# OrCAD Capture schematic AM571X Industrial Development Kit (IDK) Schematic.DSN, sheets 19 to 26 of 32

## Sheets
19 Pg06: Power Supply 2: size C
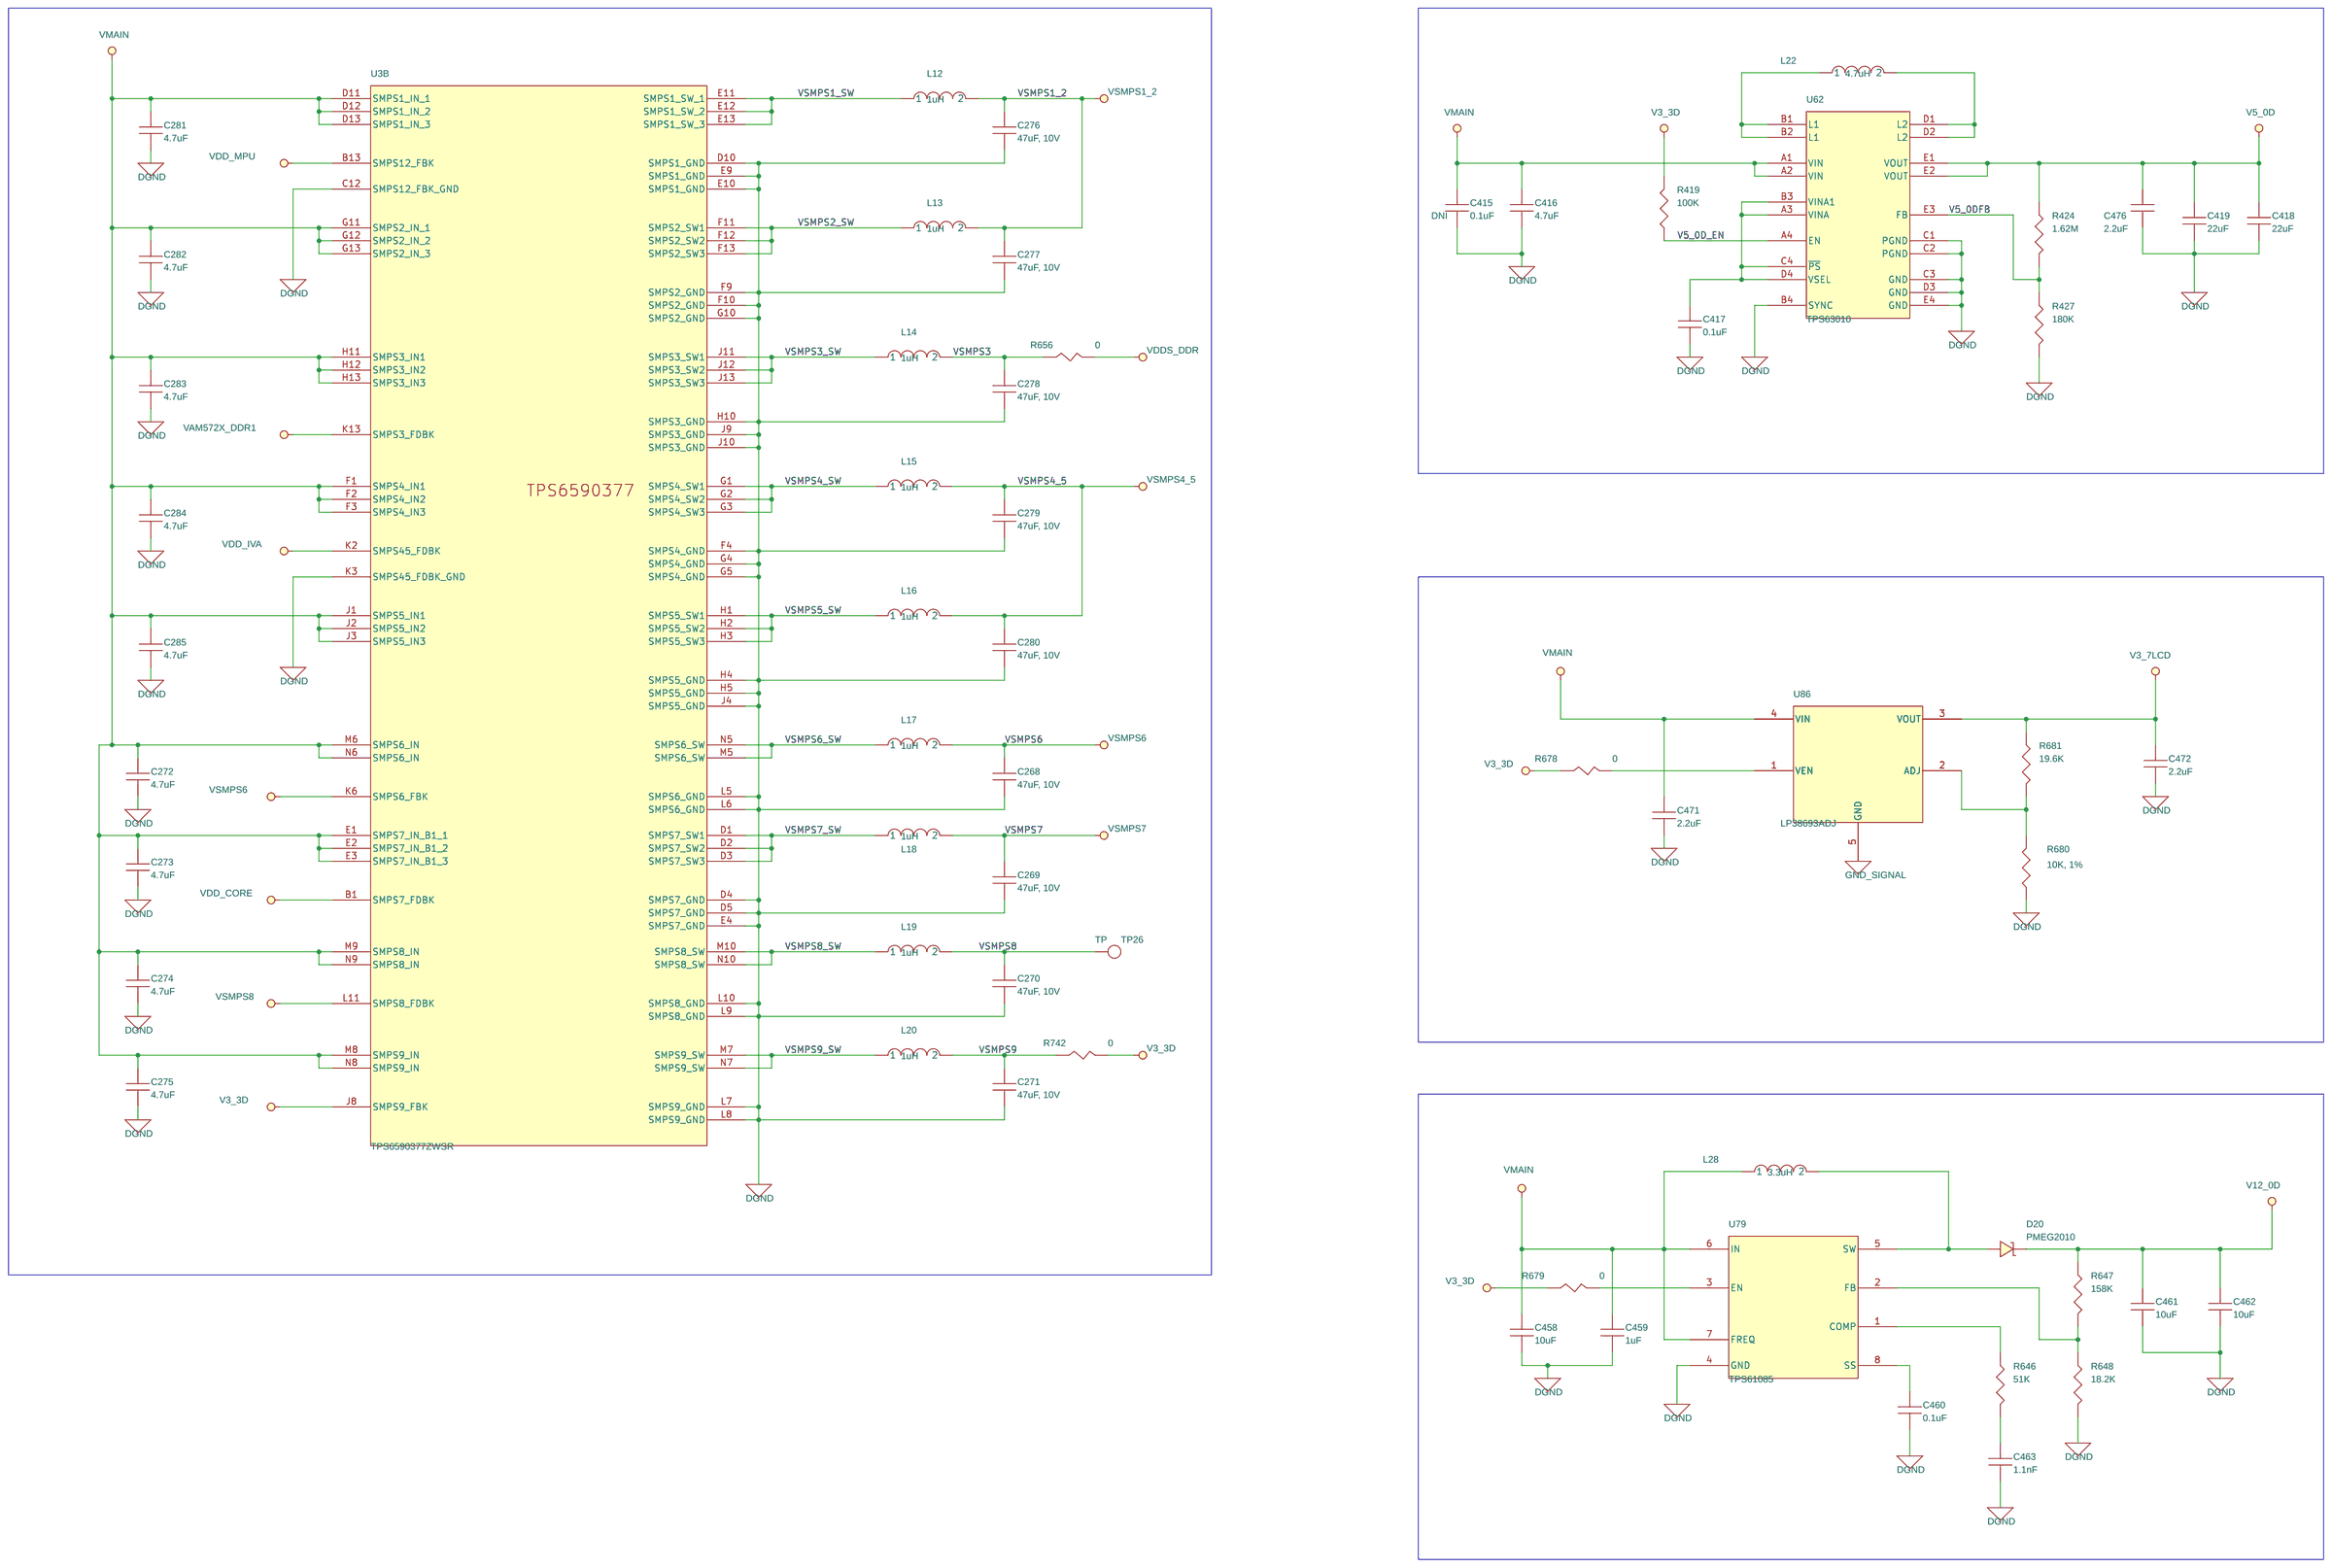
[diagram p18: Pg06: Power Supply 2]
20 Pg30: PCIE Connector: size C
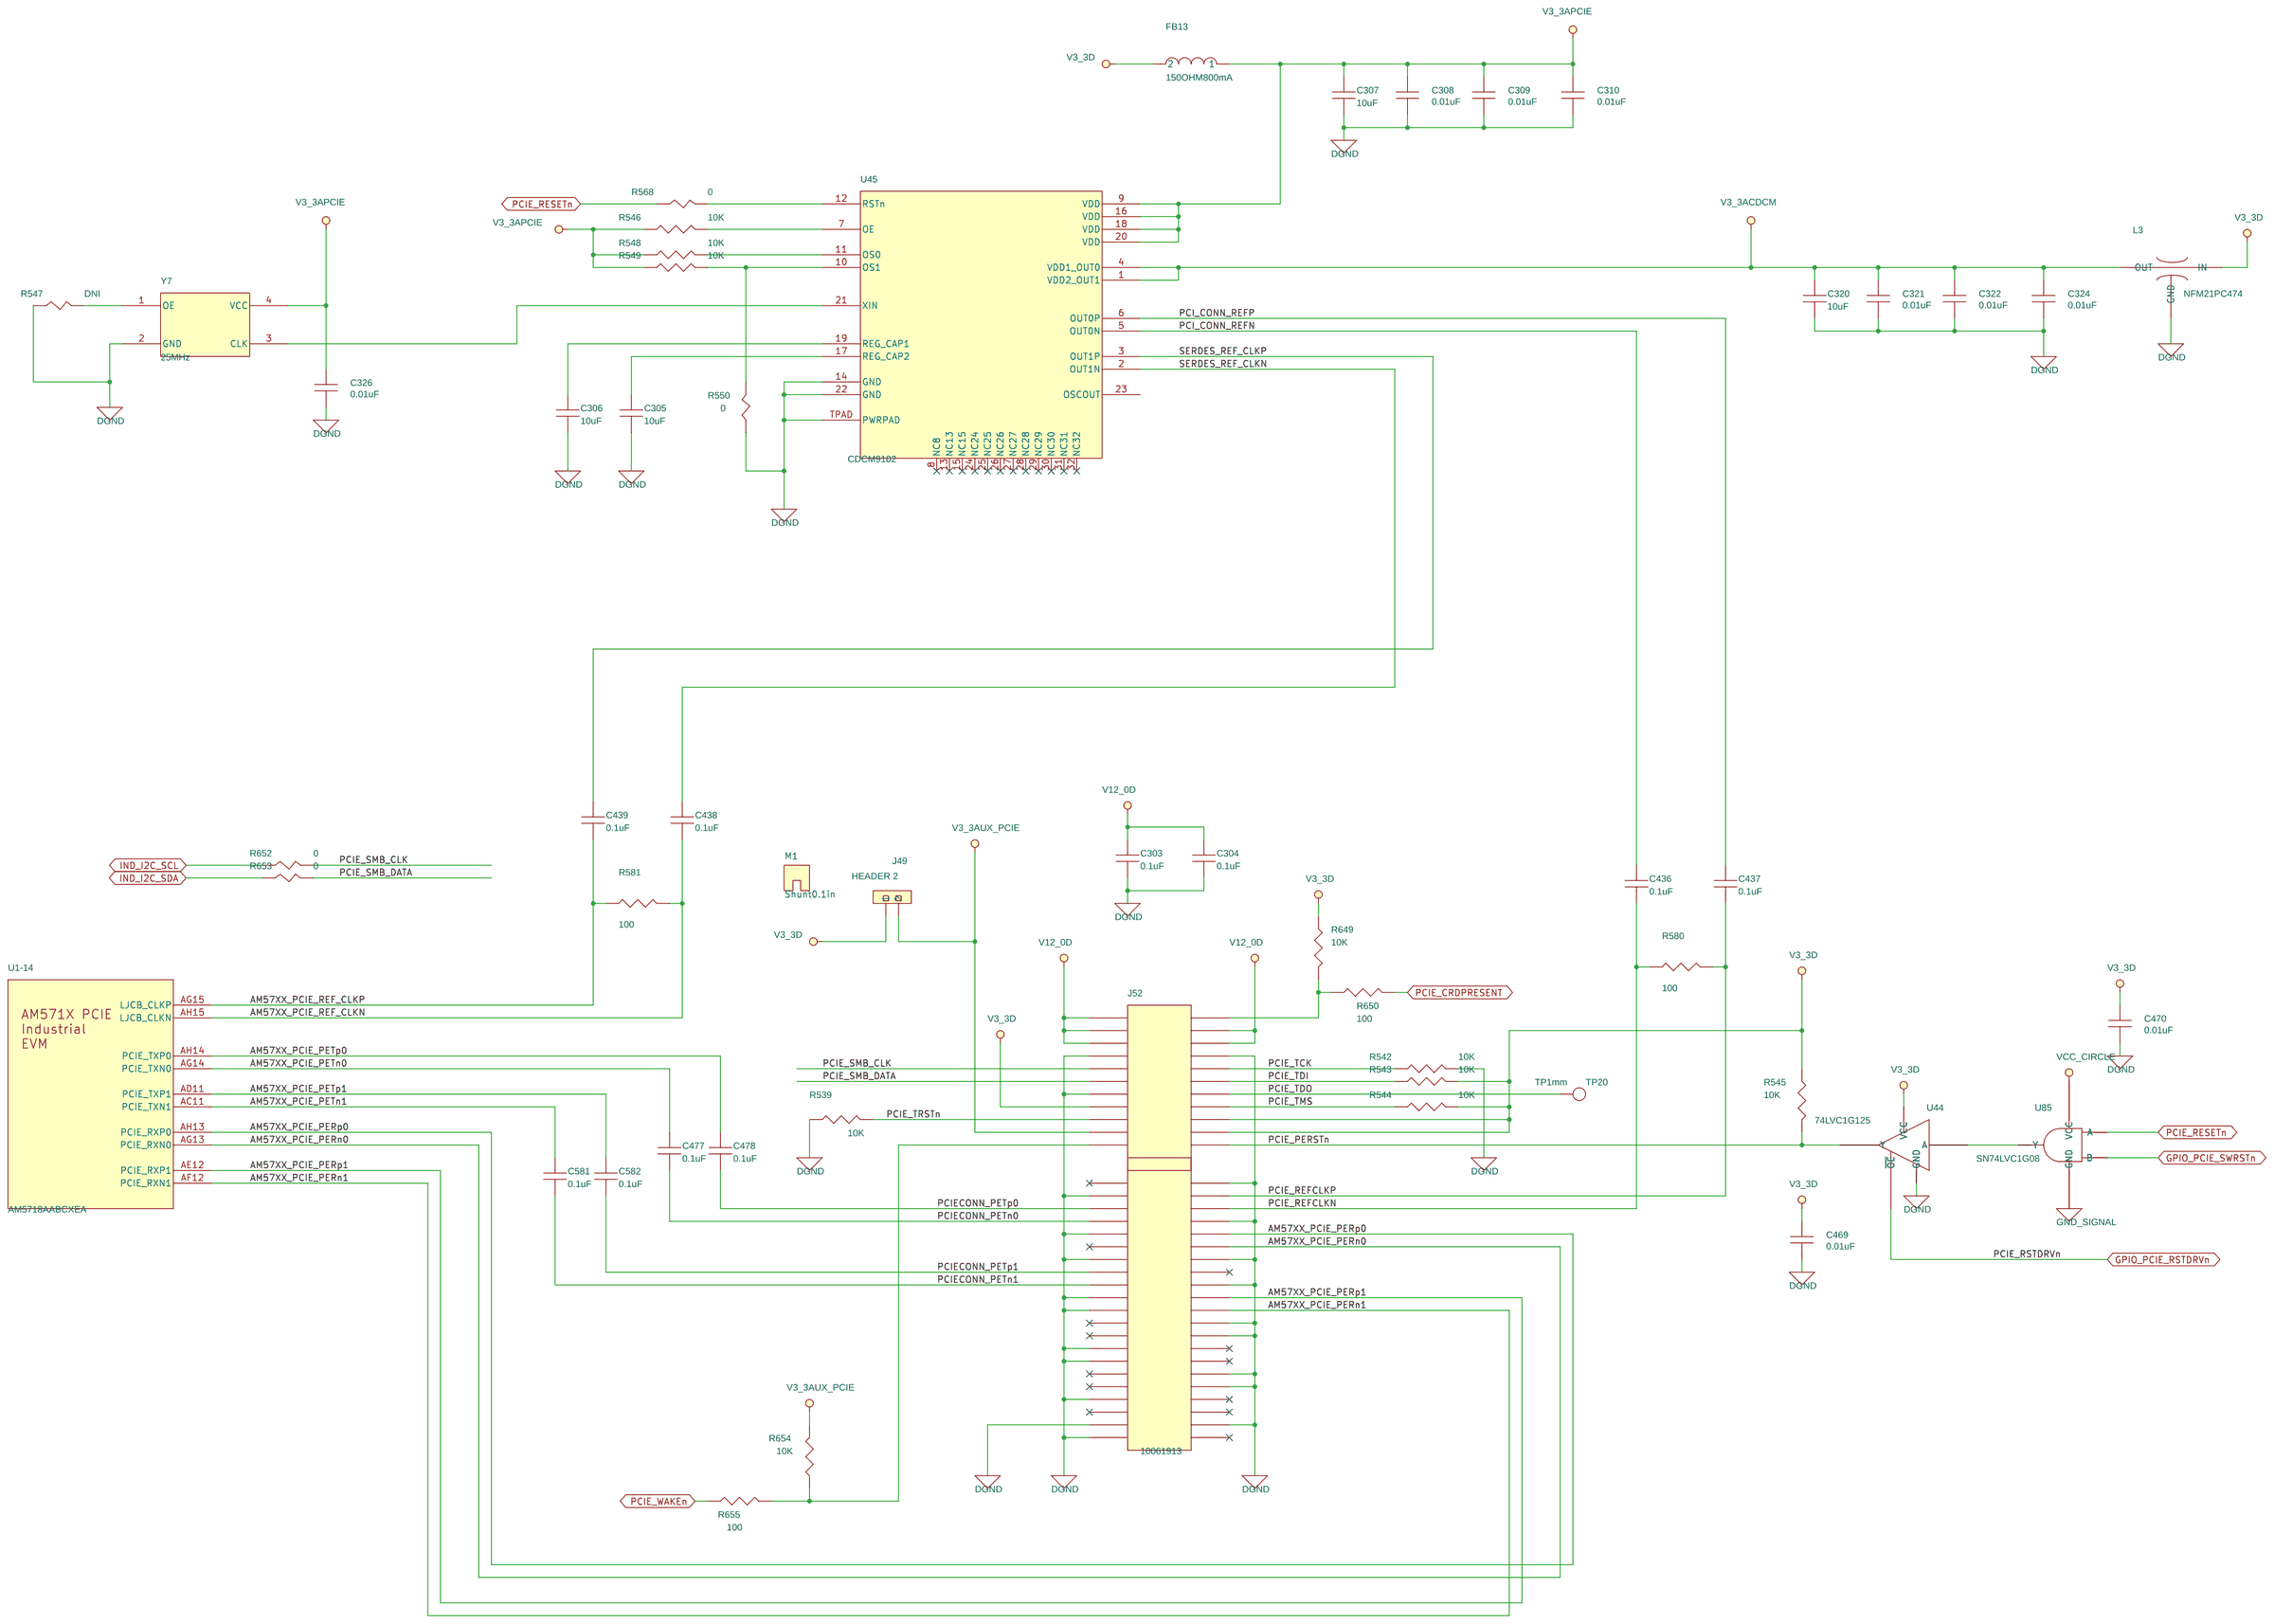
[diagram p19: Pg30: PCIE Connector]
21 Pg13: ICSS2 Ethernet 1: size C
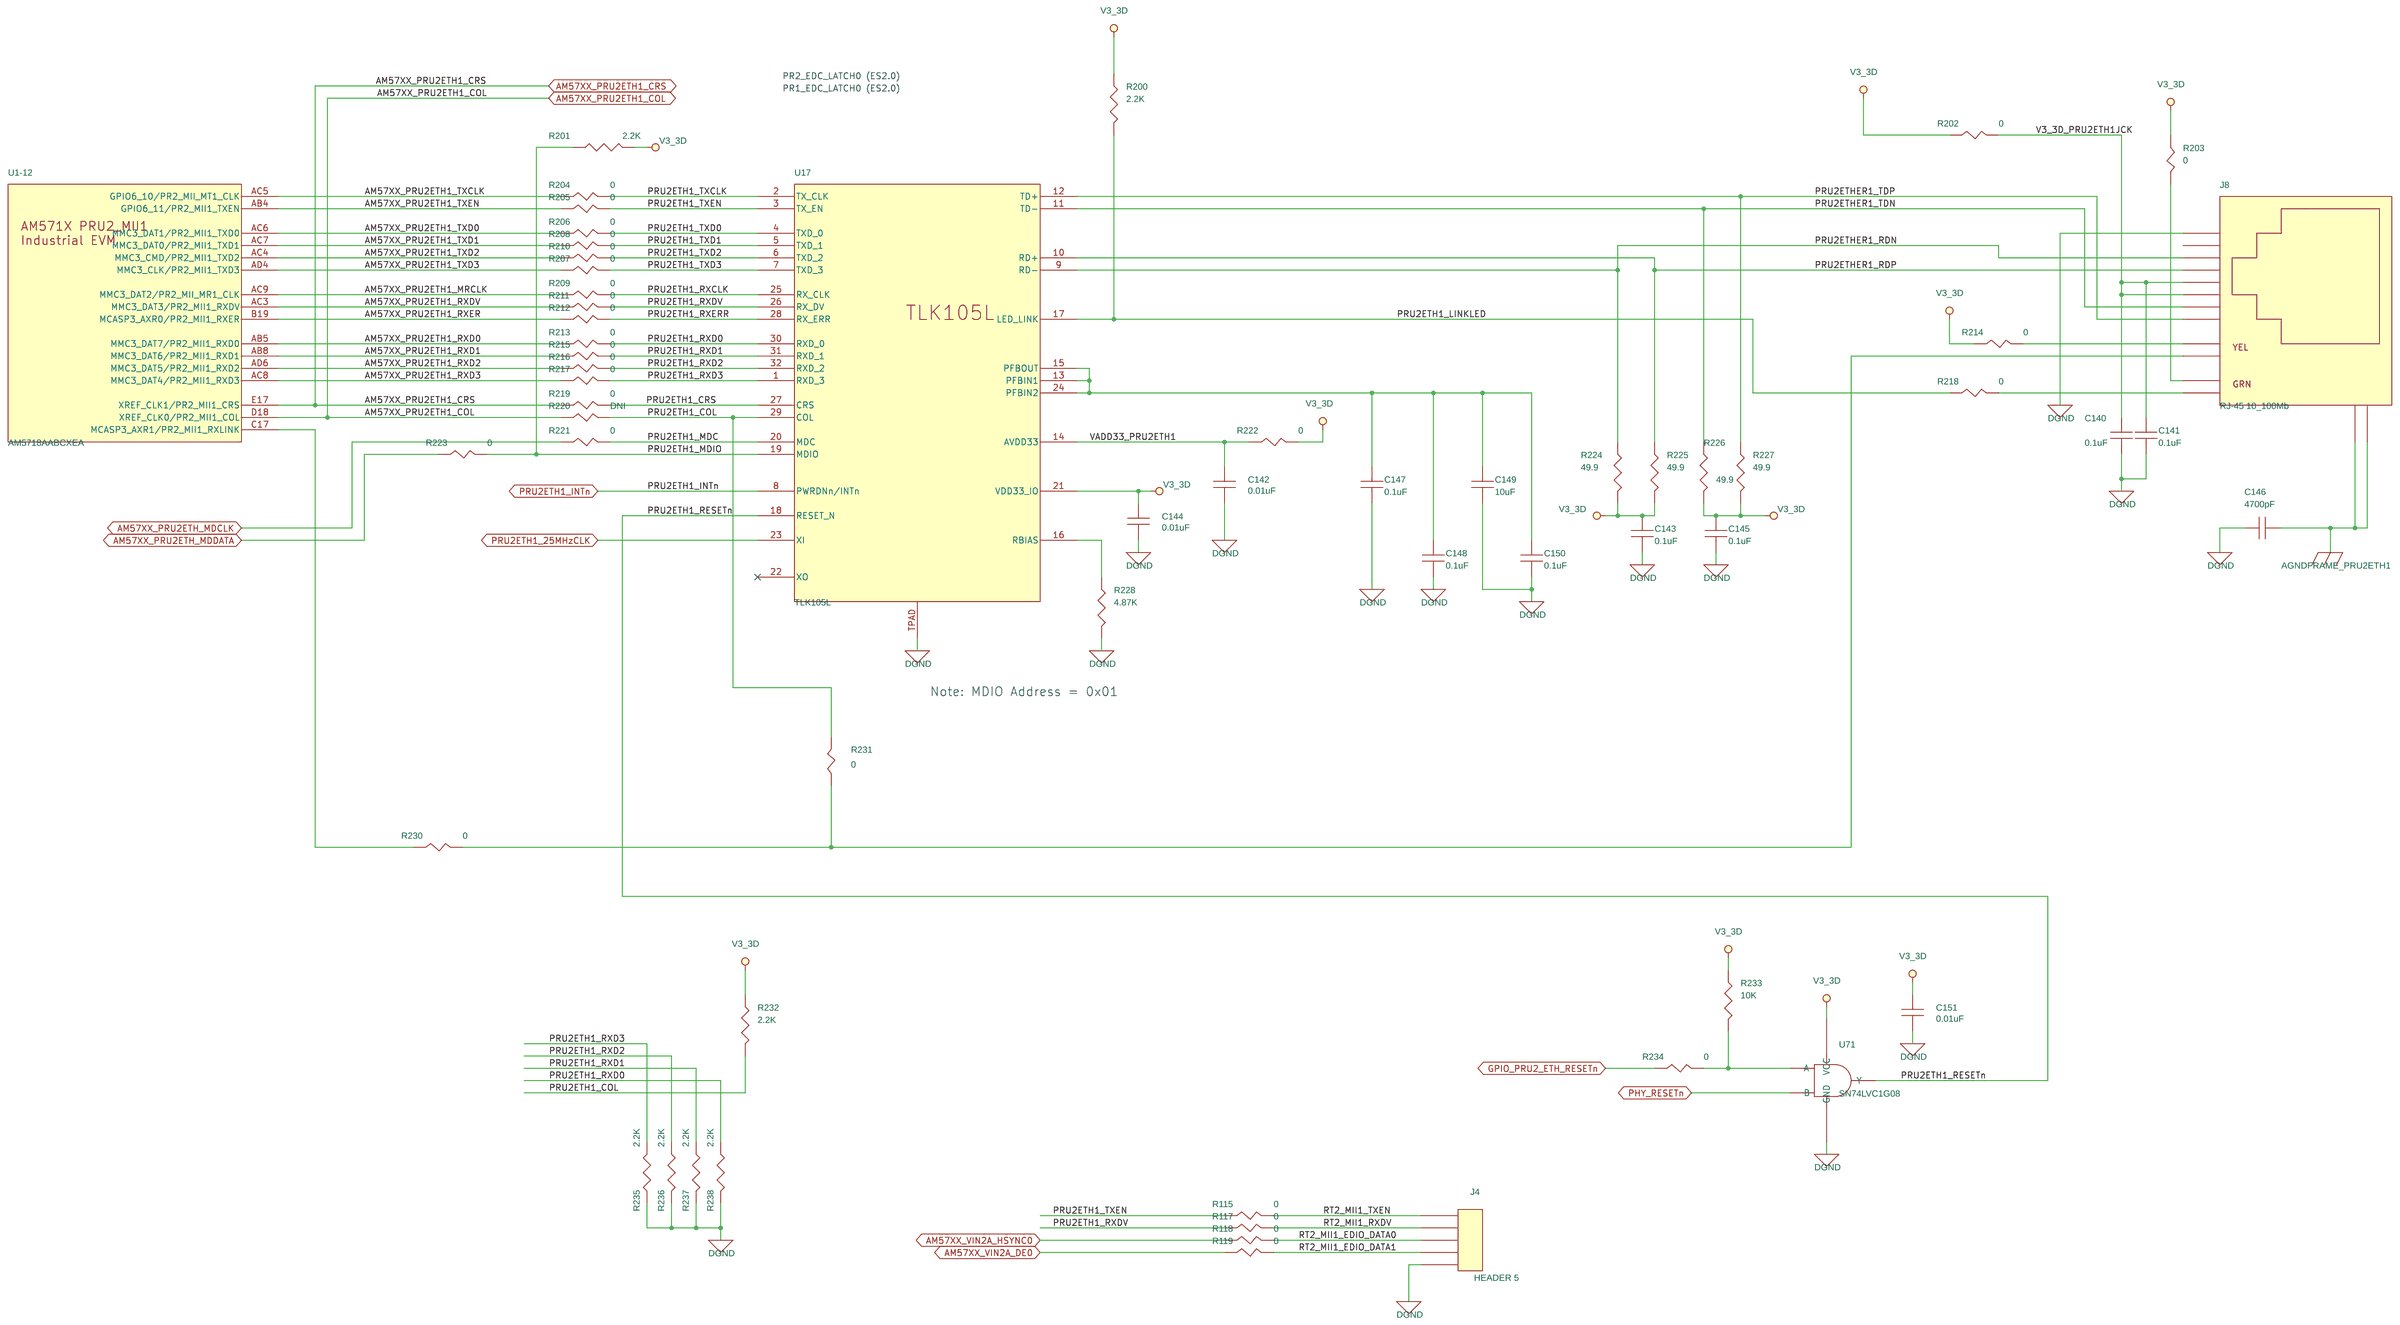
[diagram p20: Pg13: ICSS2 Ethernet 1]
22 Pg11: ICSS1 Ethernet 1: size C
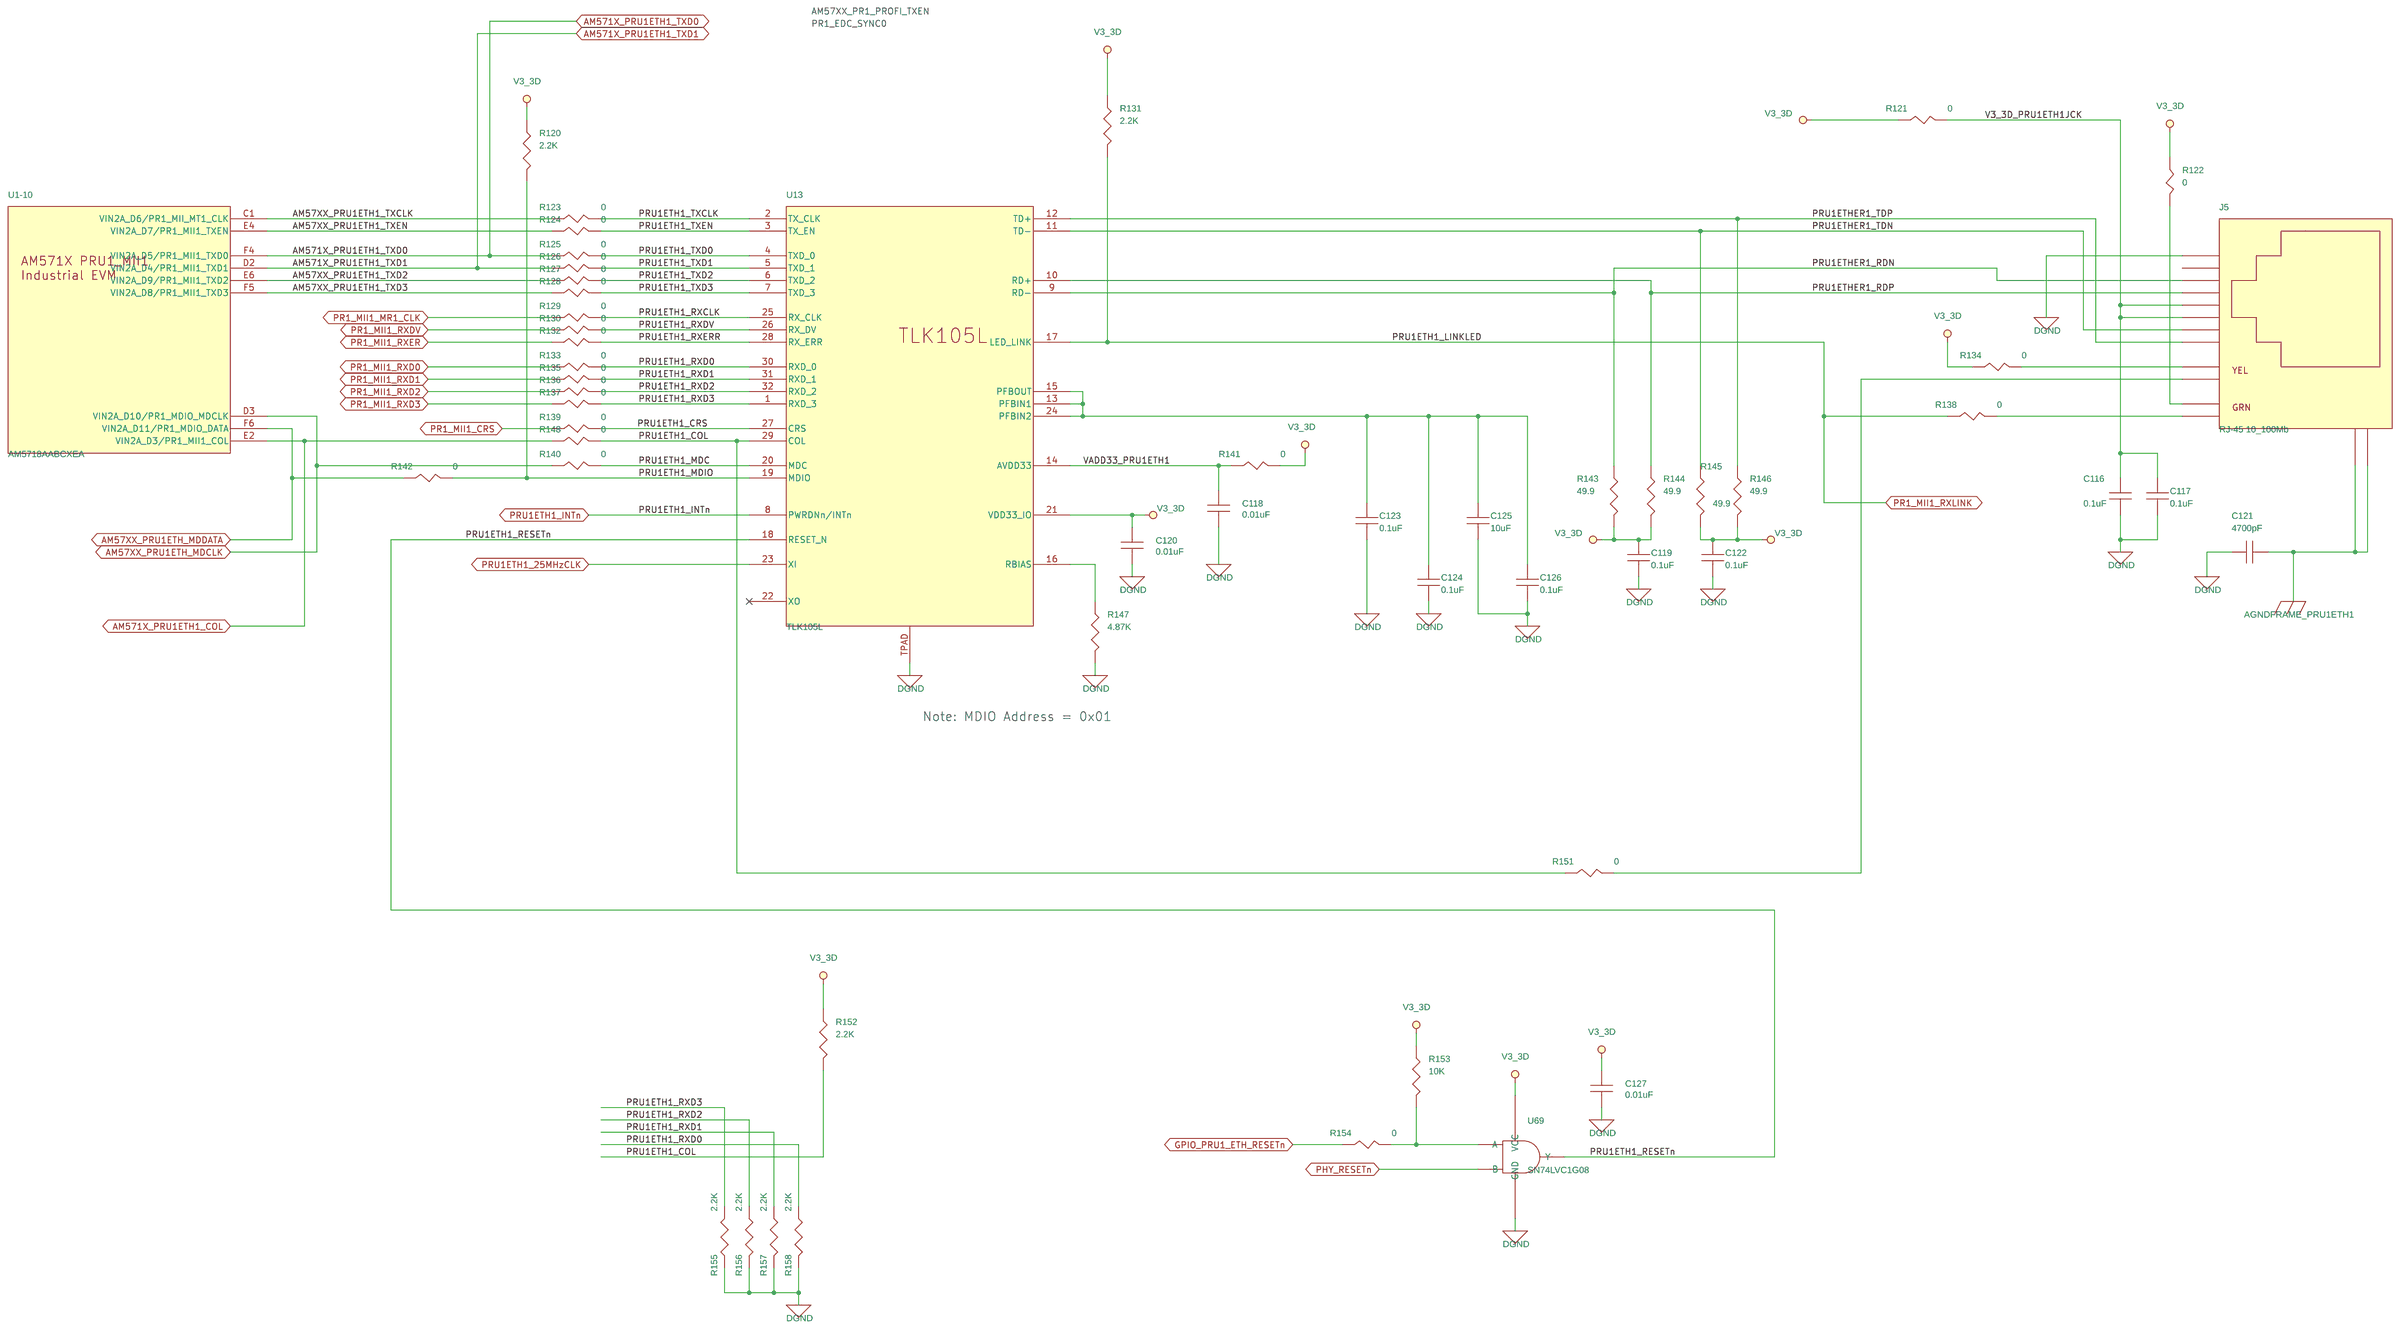
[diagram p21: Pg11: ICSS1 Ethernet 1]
23 Pg10: ICSS1 Ethernet 0: size C
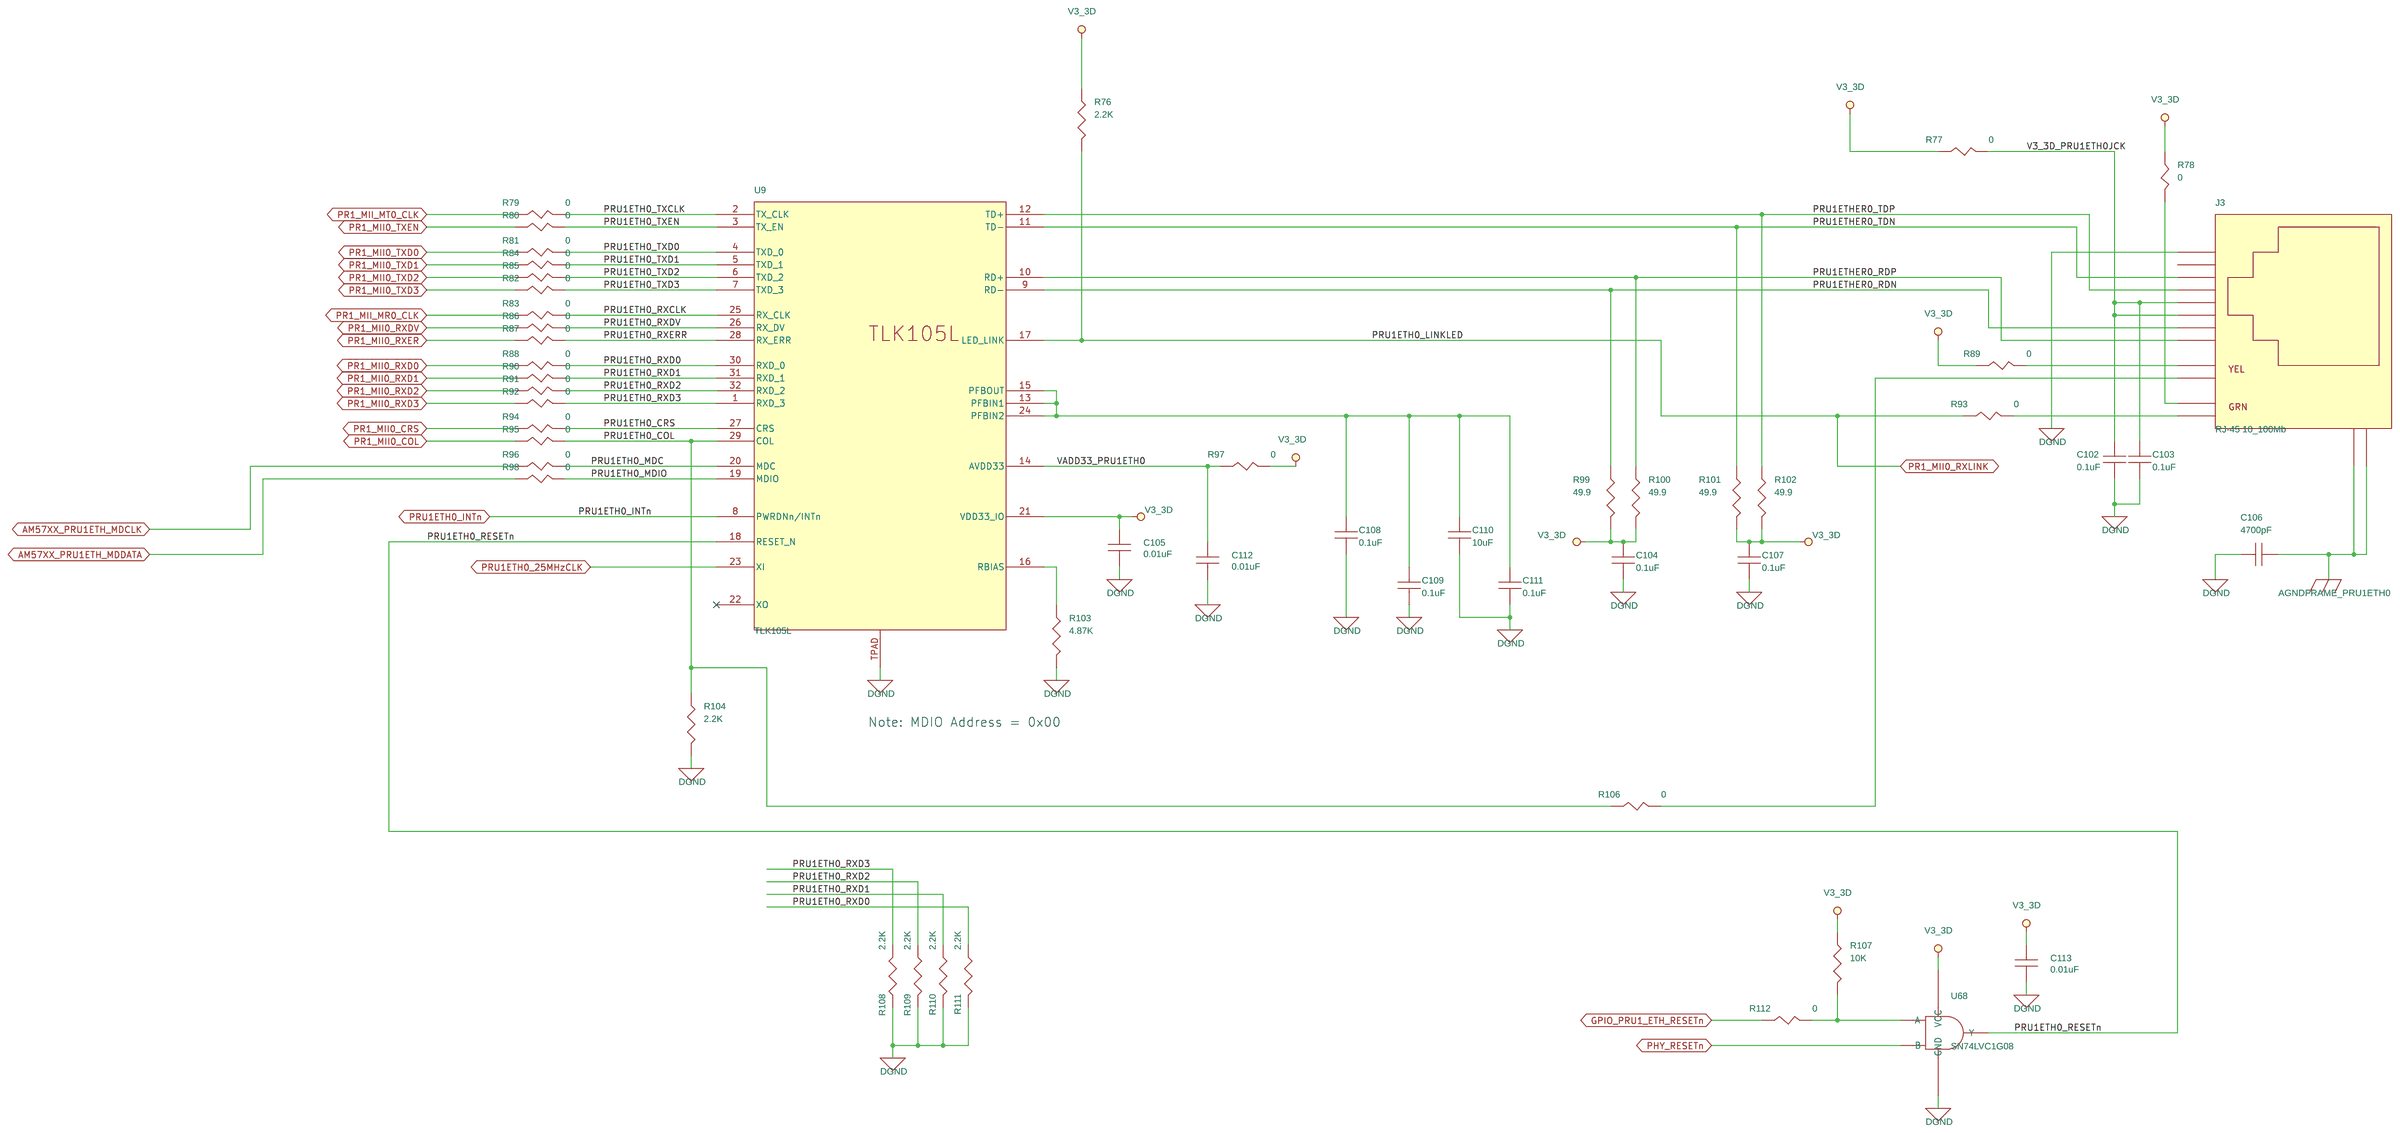
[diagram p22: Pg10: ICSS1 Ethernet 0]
24 Pg12: ICSS2 Ethernet 0: size C
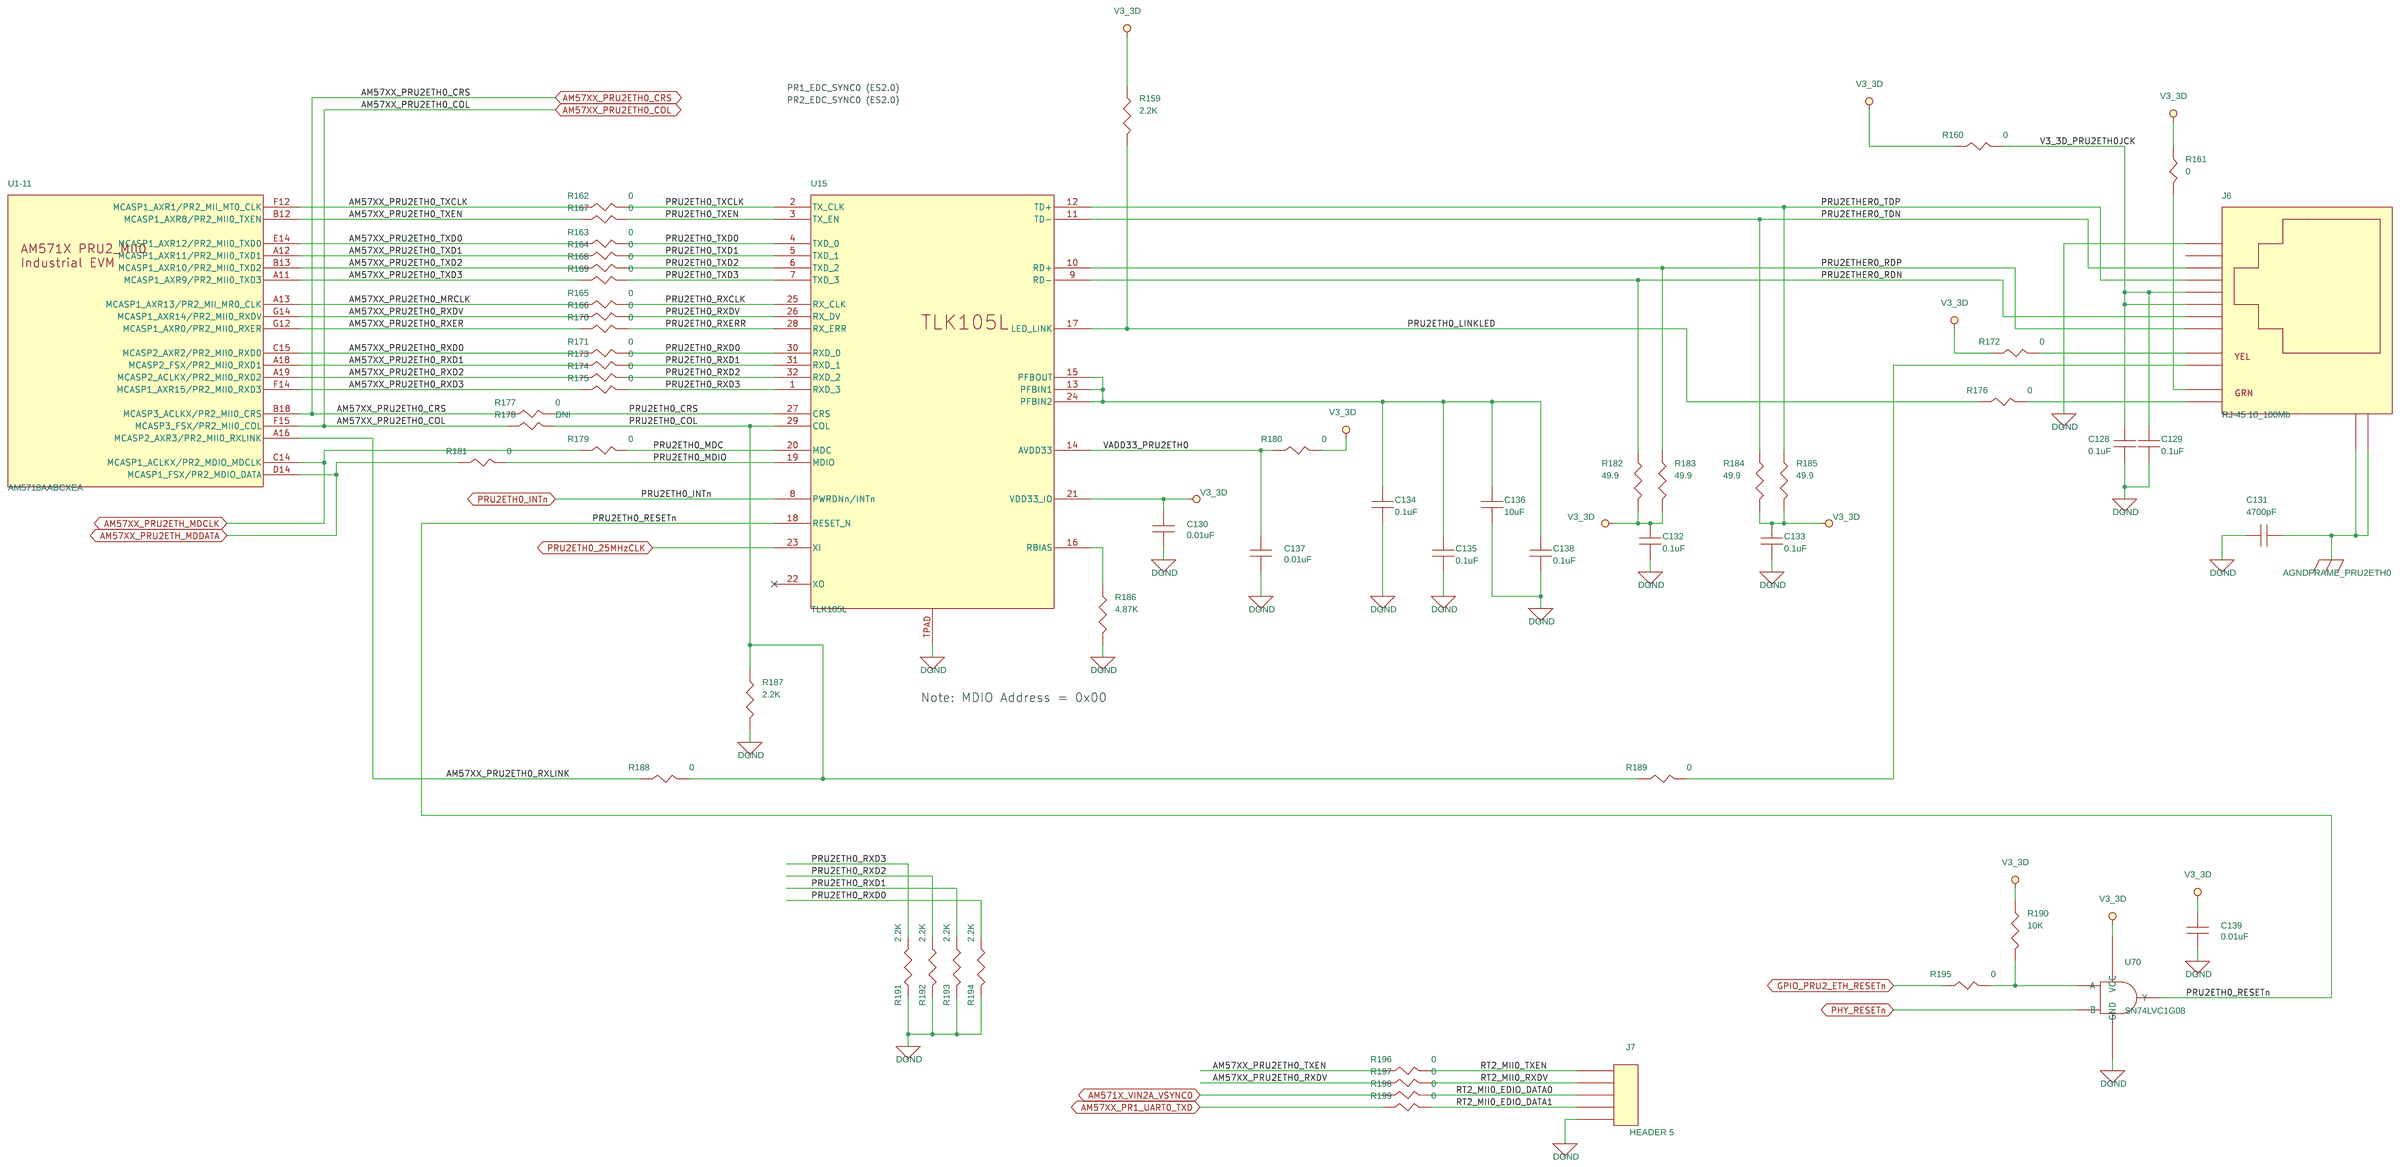
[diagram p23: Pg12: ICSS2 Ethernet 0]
25 Pg18: SDMMC #1 Interface: size C
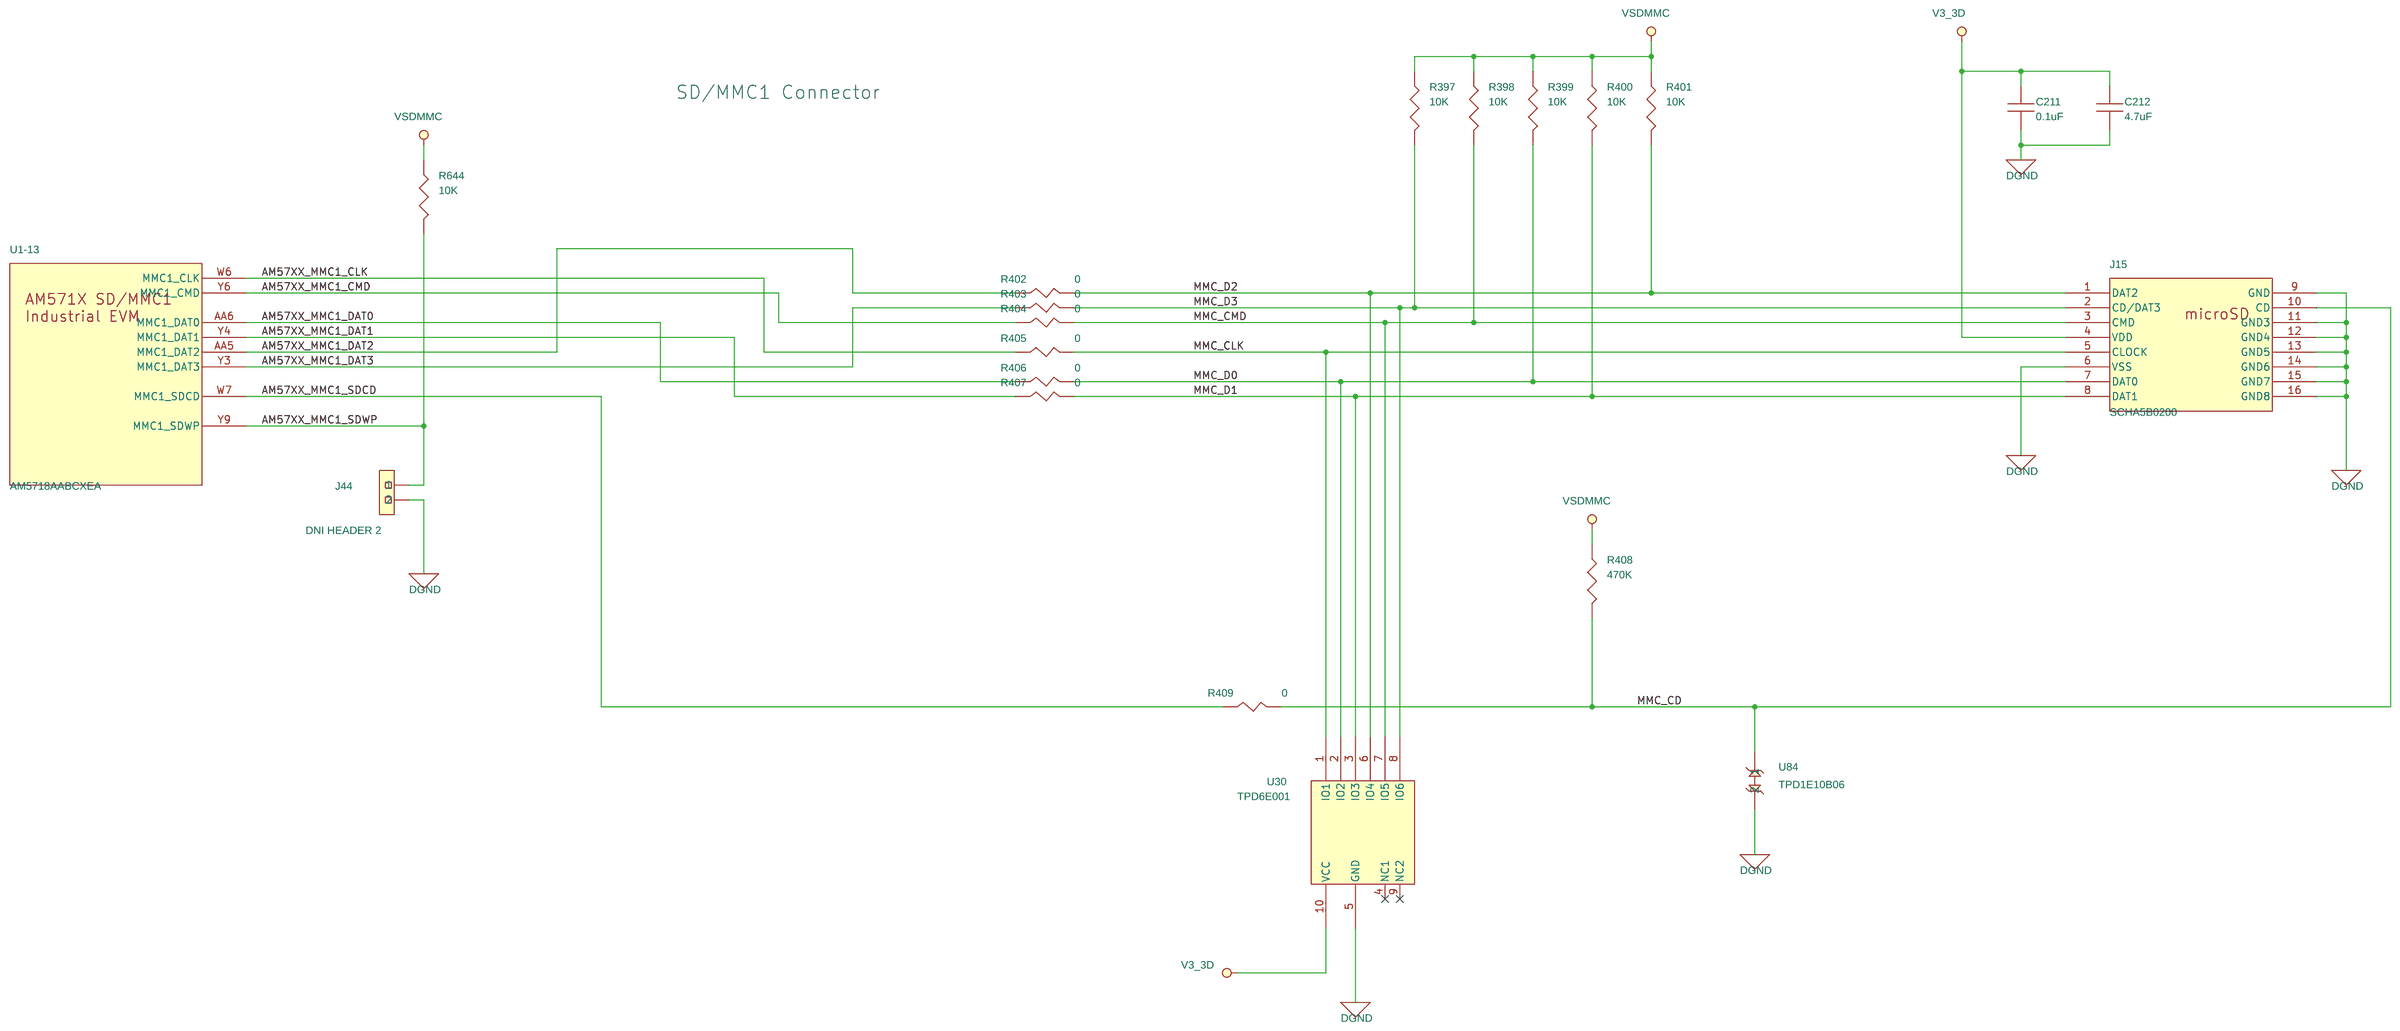
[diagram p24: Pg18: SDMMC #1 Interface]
26 Pg17: Gbit Ethernet #1: size C
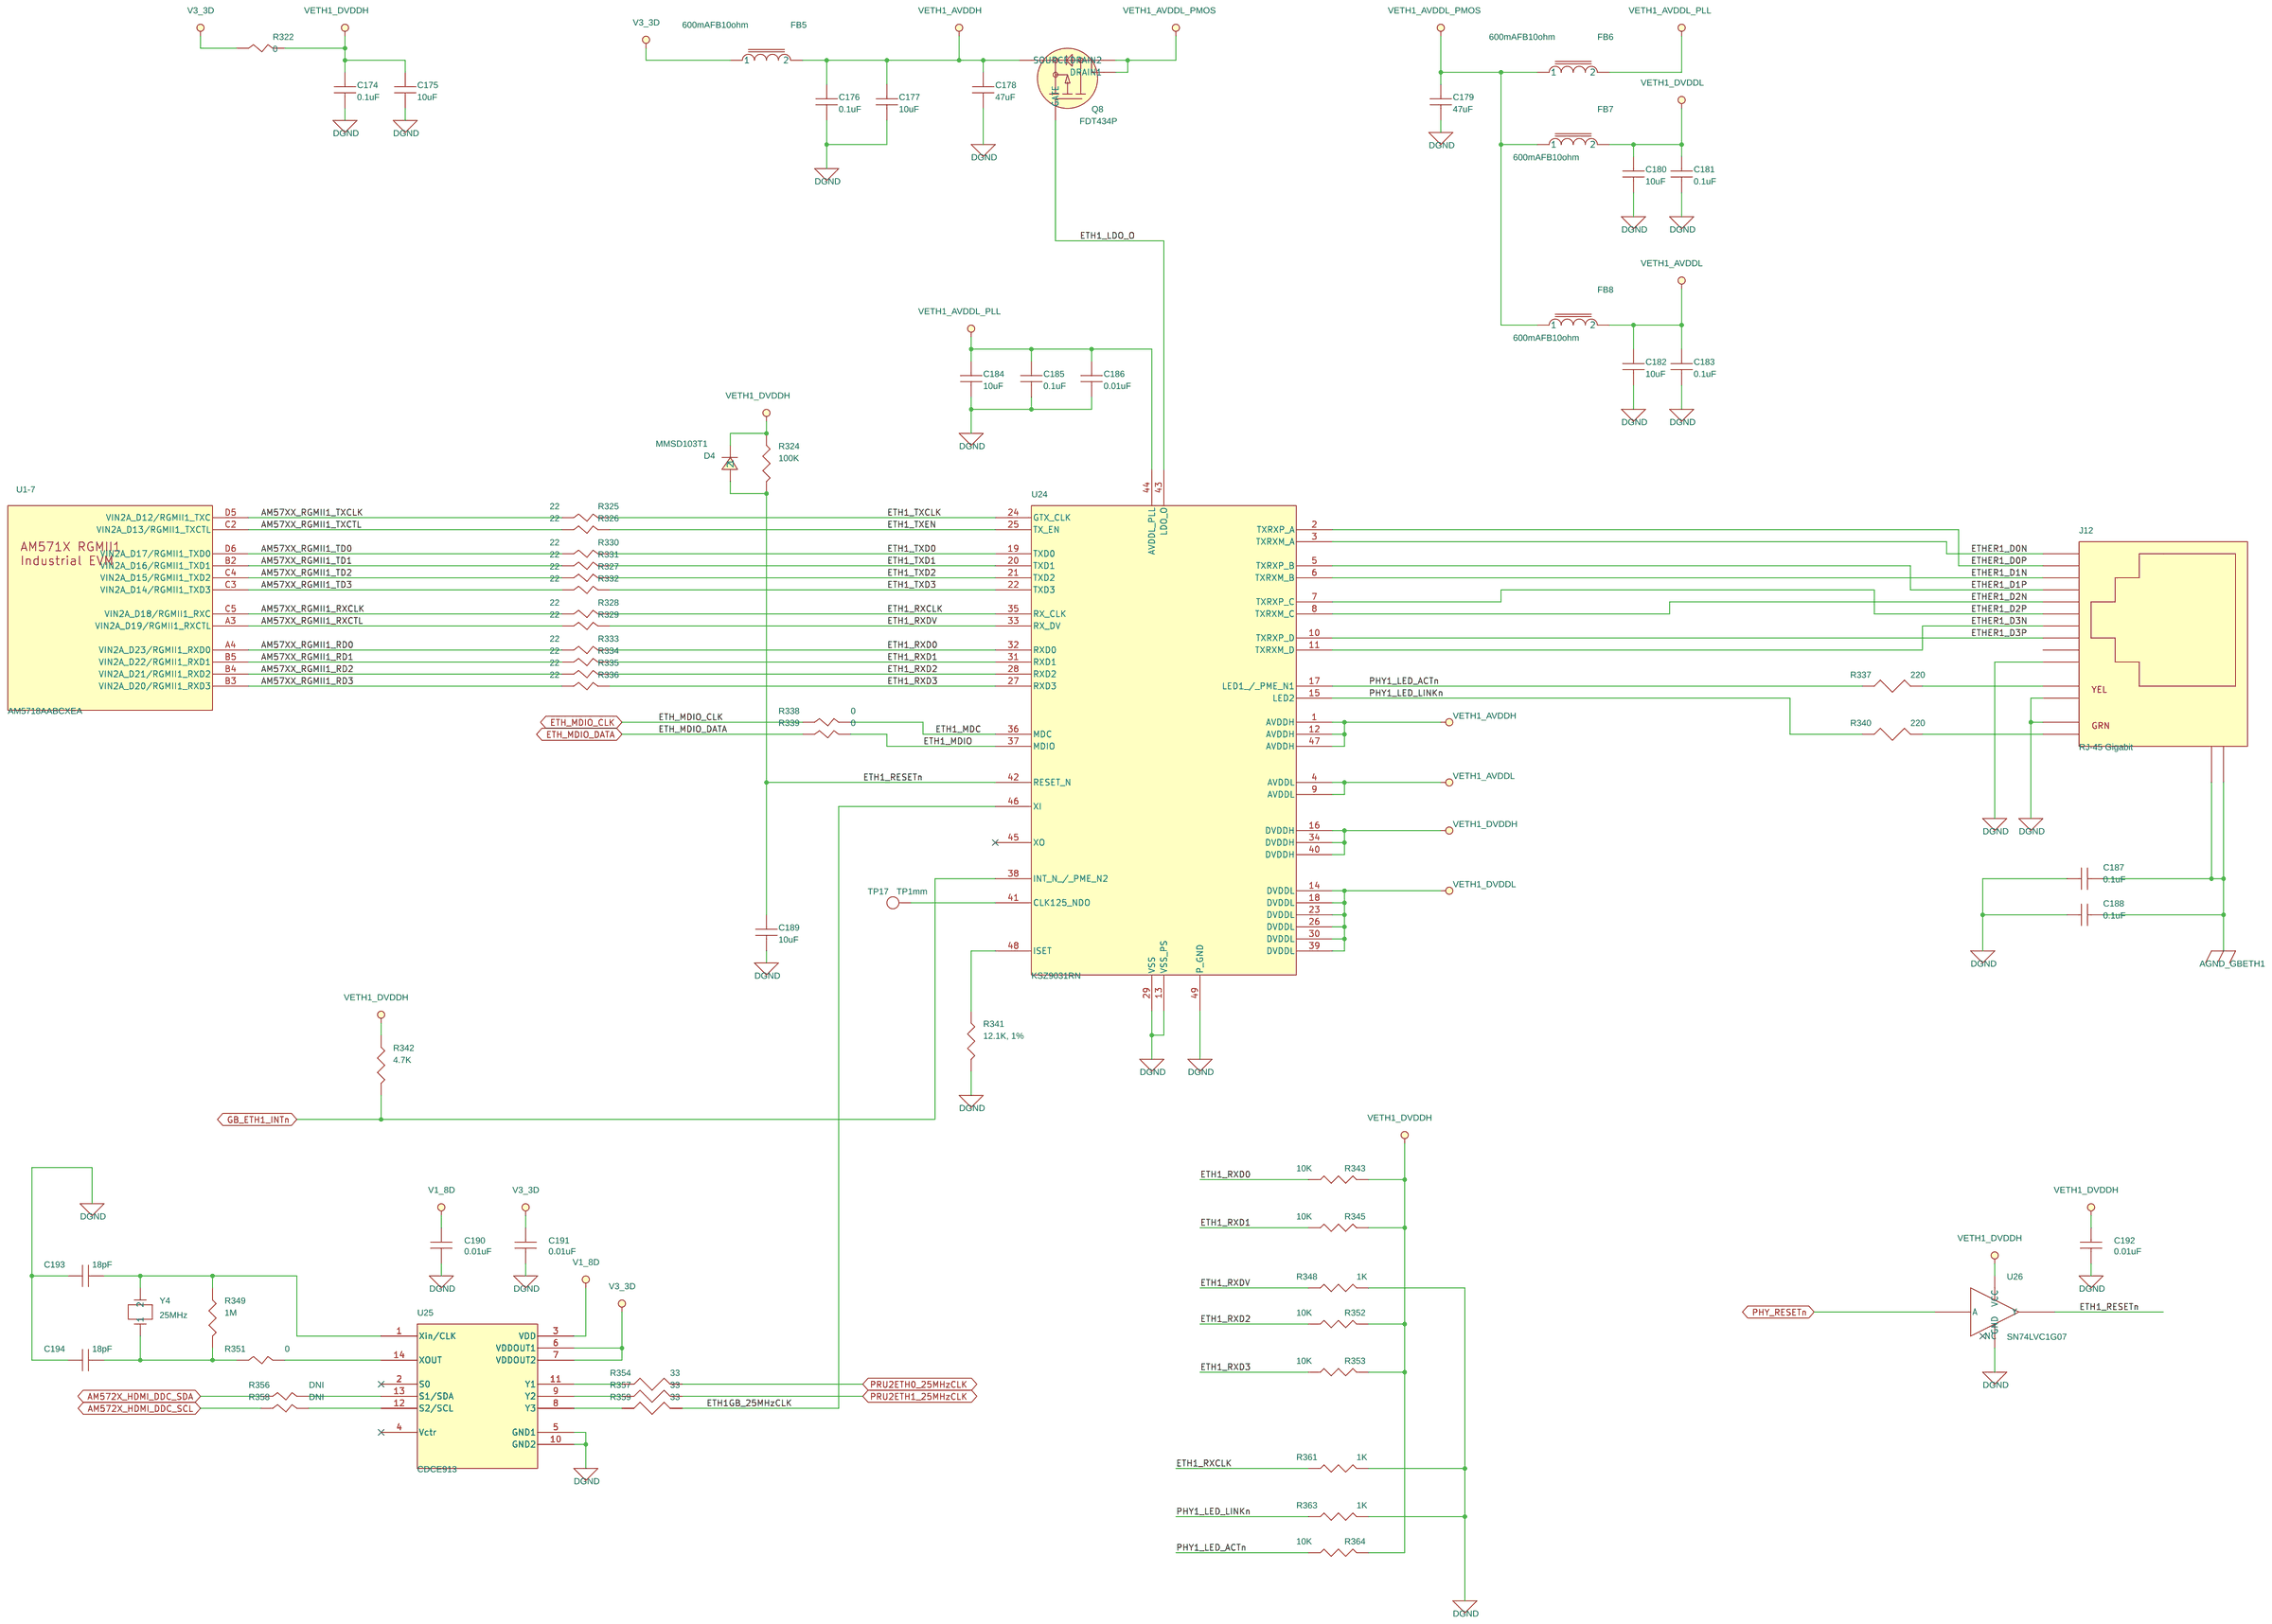
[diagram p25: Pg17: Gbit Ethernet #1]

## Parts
sheet Pg06: Power Supply 2
C268  47uF, 10V  [SM-7351-CAP-1206]
C269  47uF, 10V  [SM-7351-CAP-1206]
C270  47uF, 10V  [SM-7351-CAP-1206]
C271  47uF, 10V  [SM-7351-CAP-1206]
C272  4.7uF  [SM-7351-CAP-0603]
C273  4.7uF  [SM-7351-CAP-0603]
C274  4.7uF  [SM-7351-CAP-0603]
C275  4.7uF  [SM-7351-CAP-0603]
C276  47uF, 10V  [SM-7351-CAP-1206]
C277  47uF, 10V  [SM-7351-CAP-1206]
C278  47uF, 10V  [SM-7351-CAP-1206]
C279  47uF, 10V  [SM-7351-CAP-1206]
C280  47uF, 10V  [SM-7351-CAP-1206]
C281  4.7uF  [SM-7351-CAP-0603]
C282  4.7uF  [SM-7351-CAP-0603]
C283  4.7uF  [SM-7351-CAP-0603]
C284  4.7uF  [SM-7351-CAP-0603]
C285  4.7uF  [SM-7351-CAP-0603]
C415  0.1uF  [SM-7351-CAP-0402]
C416  4.7uF  [SM-7351-CAP-0603]
C417  0.1uF  [SM-7351-CAP-0402]
C418  22uF  [SM-7351-CAP-0805]
C419  22uF  [SM-7351-CAP-0805]
C458  10uF  [SM-7351-CAP-0805]
C459  1uF  [SM-7351-CAP-0603]
C460  0.1uF  [SM-7351-CAP-0402]
C461  10uF  [SM-7351-CAP-0805]
C462  10uF  [SM-7351-CAP-0805]
C463  1.1nF  [SM-7351-CAP-0603]
C471  2.2uF  [SM-7351-CAP-0805]
C472  2.2uF  [SM-7351-CAP-0805]
C476  2.2uF  [SM-7351-CAP-0402]
D20  PMEG2010  [DFN1006D-2]
L12  1uH  [ind_ihlp1616ab]
L13  1uH  [ind_ihlp1616ab]
L14  1uH  [ind_ihlp1616ab]
L15  1uH  [ind_ihlp1616ab]
L16  1uH  [ind_ihlp1616ab]
L17  1uH  [ind_ihlp1616ab]
L18  1uH  [ind_ihlp1616ab]
L19  1uH  [ind_ihlp1616ab]
L20  1uH  [ind_ihlp1616ab]
L22  4.7uH  [smd_slf7055t]
L28  3.3uH  [vlcf5020t]
R419  100K  [SM-7351-RES-0402]
R424  1.62M  [SM-7351-RES-0402]
R427  180K  [SM-7351-RES-0402]
R646  51K  [SM-7351-RES-0402]
R647  158K  [SM-7351-RES-0402]
R648  18.2K  [SM-7351-RES-0402]
R656  0  [SM-7351-RES-0603]
R678  0  [SM-7351-RES-0402]
R679  0  [SM-7351-RES-0402]
R680  10K, 1%  [SM-7351-RES-0402]
R681  19.6K  [SM-7351-RES-0402]
R742  0  [SM-7351-RES-0603]
TP26  TP  [TH_TP_5002]
U3  TPS6590377ZWSR  [bga12x12-169-55m]  (sections A,B)
U62  TPS63010  [u_20_dsbga]
U79  TPS61085  [MSOP3X3-8-43M]
U86  LP38693ADJ  [SOT-223-5]
sheet Pg10: ICSS1 Ethernet 0
C102  0.1uF  [SM-7351-CAP-0402]
C103  0.1uF  [SM-7351-CAP-0402]
C104  0.1uF  [SM-7351-CAP-0402]
C105  0.01uF  [SM-7351-CAP-0402]
C106  4700pF  [SM-7351-CAP-0402]
C107  0.1uF  [SM-7351-CAP-0402]
C108  0.1uF  [SM-7351-CAP-0402]
C109  0.1uF  [SM-7351-CAP-0402]
C110  10uF  [SM-7351-CAP-0805]
C111  0.1uF  [SM-7351-CAP-0402]
C112  0.01uF  [SM-7351-CAP-0402]
C113  0.01uF  [SM-7351-CAP-0402]
J3  RJ-45 10_100Mb  [CNRJ45-1X1WLED]
R76  2.2K  [sm-7351-res-0402]
R77  0  [SM-7351-RES-0402]
R78  0  [SM-7351-RES-0402]
R79  0  [SM-7351-RES-0402]
R80  0  [SM-7351-RES-0402]
R81  0  [SM-7351-RES-0402]
R82  0  [SM-7351-RES-0402]
R83  0  [SM-7351-RES-0402]
R84  0  [SM-7351-RES-0402]
R85  0  [SM-7351-RES-0402]
R86  0  [SM-7351-RES-0402]
R87  0  [SM-7351-RES-0402]
R88  0  [SM-7351-RES-0402]
R89  0  [SM-7351-RES-0402]
R90  0  [SM-7351-RES-0402]
R91  0  [SM-7351-RES-0402]
R92  0  [SM-7351-RES-0402]
R93  0  [SM-7351-RES-0402]
R94  0  [SM-7351-RES-0402]
R95  0  [SM-7351-RES-0402]
R96  0  [SM-7351-RES-0402]
R97  0  [SM-7351-RES-0603]
R98  0  [SM-7351-RES-0402]
R99  49.9  [SM-7351-RES-0402]
R100  49.9  [SM-7351-RES-0402]
R101  49.9  [SM-7351-RES-0402]
R102  49.9  [SM-7351-RES-0402]
R103  4.87K  [SM-7351-RES-0402]
R104  2.2K  [sm-7351-res-0402]
R106  0  [SM-7351-RES-0402]
R107  10K  [SM-7351-RES-0402]
R108  2.2K  [sm-7351-res-0402]
R109  2.2K  [sm-7351-res-0402]
R110  2.2K  [sm-7351-res-0402]
R111  2.2K  [sm-7351-res-0402]
R112  0  [SM-7351-RES-0402]
U9  TLK105L  [qfn5x5-32-39m]
U68  SN74LVC1G08  [sm-so-sc70-5]
sheet Pg11: ICSS1 Ethernet 1
C116  0.1uF  [SM-7351-CAP-0402]
C117  0.1uF  [SM-7351-CAP-0402]
C118  0.01uF  [SM-7351-CAP-0402]
C119  0.1uF  [SM-7351-CAP-0402]
C120  0.01uF  [SM-7351-CAP-0402]
C121  4700pF  [SM-7351-CAP-0402]
C122  0.1uF  [SM-7351-CAP-0402]
C123  0.1uF  [SM-7351-CAP-0402]
C124  0.1uF  [SM-7351-CAP-0402]
C125  10uF  [SM-7351-CAP-0805]
C126  0.1uF  [SM-7351-CAP-0402]
C127  0.01uF  [SM-7351-CAP-0402]
J5  RJ-45 10_100Mb  [CNRJ45-1X1WLED]
R120  2.2K  [sm-7351-res-0402]
R121  0  [SM-7351-RES-0402]
R122  0  [SM-7351-RES-0402]
R123  0  [SM-7351-RES-0402]
R124  0  [SM-7351-RES-0402]
R125  0  [SM-7351-RES-0402]
R126  0  [SM-7351-RES-0402]
R127  0  [SM-7351-RES-0402]
R128  0  [SM-7351-RES-0402]
R129  0  [SM-7351-RES-0402]
R130  0  [SM-7351-RES-0402]
R131  2.2K  [sm-7351-res-0402]
R132  0  [SM-7351-RES-0402]
R133  0  [SM-7351-RES-0402]
R134  0  [SM-7351-RES-0402]
R135  0  [SM-7351-RES-0402]
R136  0  [SM-7351-RES-0402]
R137  0  [SM-7351-RES-0402]
R138  0  [SM-7351-RES-0603]
R139  0  [SM-7351-RES-0402]
R140  0  [SM-7351-RES-0402]
R141  0  [SM-7351-RES-0603]
R142  0  [SM-7351-RES-0402]
R143  49.9  [SM-7351-RES-0402]
R144  49.9  [SM-7351-RES-0402]
R145  49.9  [SM-7351-RES-0402]
R146  49.9  [SM-7351-RES-0402]
R147  4.87K  [SM-7351-RES-0402]
R148  0  [SM-7351-RES-0402]
R151  0  [SM-7351-RES-0402]
R152  2.2K  [sm-7351-res-0402]
R153  10K  [SM-7351-RES-0402]
R154  0  [SM-7351-RES-0402]
R155  2.2K  [sm-7351-res-0402]
R156  2.2K  [sm-7351-res-0402]
R157  2.2K  [sm-7351-res-0402]
R158  2.2K  [sm-7351-res-0402]
U13  TLK105L  [qfn5x5-32-39m]
U69  SN74LVC1G08  [sm-so-sc70-5]
sheet Pg12: ICSS2 Ethernet 0
C128  0.1uF  [SM-7351-CAP-0402]
C129  0.1uF  [SM-7351-CAP-0402]
C130  0.01uF  [SM-7351-CAP-0402]
C131  4700pF  [SM-7351-CAP-0402]
C132  0.1uF  [SM-7351-CAP-0402]
C133  0.1uF  [SM-7351-CAP-0402]
C134  0.1uF  [SM-7351-CAP-0402]
C135  0.1uF  [SM-7351-CAP-0402]
C136  10uF  [SM-7351-CAP-0805]
C137  0.01uF  [SM-7351-CAP-0402]
C138  0.1uF  [SM-7351-CAP-0402]
C139  0.01uF  [SM-7351-CAP-0402]
J6  RJ-45 10_100Mb  [CNRJ45-1X1WLED]
J7  HEADER 5  [HEADER_5X1]
R159  2.2K  [sm-7351-res-0402]
R160  0  [SM-7351-RES-0402]
R161  0  [SM-7351-RES-0402]
R162  0  [SM-7351-RES-0402]
R163  0  [SM-7351-RES-0402]
R164  0  [SM-7351-RES-0402]
R165  0  [SM-7351-RES-0402]
R166  0  [SM-7351-RES-0402]
R167  0  [SM-7351-RES-0402]
R168  0  [SM-7351-RES-0402]
R169  0  [SM-7351-RES-0402]
R170  0  [SM-7351-RES-0402]
R171  0  [SM-7351-RES-0402]
R172  0  [SM-7351-RES-0402]
R173  0  [SM-7351-RES-0402]
R174  0  [SM-7351-RES-0402]
R175  0  [SM-7351-RES-0402]
R176  0  [SM-7351-RES-0402]
R177  0  [SM-7351-RES-0402]
R178  DNI  [SM-7351-RES-0402]
R179  0  [SM-7351-RES-0402]
R180  0  [SM-7351-RES-0603]
R181  0  [SM-7351-RES-0402]
R182  49.9  [SM-7351-RES-0402]
R183  49.9  [SM-7351-RES-0402]
R184  49.9  [SM-7351-RES-0402]
R185  49.9  [SM-7351-RES-0402]
R186  4.87K  [SM-7351-RES-0402]
R187  2.2K  [sm-7351-res-0402]
R188  0  [SM-7351-RES-0402]
R189  0  [SM-7351-RES-0402]
R190  10K  [SM-7351-RES-0402]
R191  2.2K  [sm-7351-res-0402]
R192  2.2K  [sm-7351-res-0402]
R193  2.2K  [sm-7351-res-0402]
R194  2.2K  [sm-7351-res-0402]
R195  0  [SM-7351-RES-0402]
R196  0  [SM-7351-RES-0402]
R197  0  [SM-7351-RES-0402]
R198  0  [SM-7351-RES-0402]
R199  0  [SM-7351-RES-0402]
U15  TLK105L  [qfn5x5-32-39m]
U70  SN74LVC1G08  [sm-so-sc70-5]
sheet Pg13: ICSS2 Ethernet 1
C140  0.1uF  [SM-7351-CAP-0402]
C141  0.1uF  [SM-7351-CAP-0402]
C142  0.01uF  [SM-7351-CAP-0402]
C143  0.1uF  [SM-7351-CAP-0402]
C144  0.01uF  [SM-7351-CAP-0402]
C145  0.1uF  [SM-7351-CAP-0402]
C146  4700pF  [SM-7351-CAP-0402]
C147  0.1uF  [SM-7351-CAP-0402]
C148  0.1uF  [SM-7351-CAP-0402]
C149  10uF  [SM-7351-CAP-0805]
C150  0.1uF  [SM-7351-CAP-0402]
C151  0.01uF  [SM-7351-CAP-0402]
J4  HEADER 5  [HEADER_5X1]
J8  RJ-45 10_100Mb  [CNRJ45-1X1WLED]
R115  0  [SM-7351-RES-0402]
R117  0  [SM-7351-RES-0402]
R118  0  [SM-7351-RES-0402]
R119  0  [SM-7351-RES-0402]
R200  2.2K  [sm-7351-res-0402]
R201  2.2K  [sm-7351-res-0402]
R202  0  [SM-7351-RES-0402]
R203  0  [SM-7351-RES-0402]
R204  0  [SM-7351-RES-0402]
R205  0  [SM-7351-RES-0402]
R206  0  [SM-7351-RES-0402]
R207  0  [SM-7351-RES-0402]
R208  0  [SM-7351-RES-0402]
R209  0  [SM-7351-RES-0402]
R210  0  [SM-7351-RES-0402]
R211  0  [SM-7351-RES-0402]
R212  0  [SM-7351-RES-0402]
R213  0  [SM-7351-RES-0402]
R214  0  [SM-7351-RES-0402]
R215  0  [SM-7351-RES-0402]
R216  0  [SM-7351-RES-0402]
R217  0  [SM-7351-RES-0402]
R218  0  [SM-7351-RES-0603]
R219  0  [SM-7351-RES-0402]
R220  DNI  [SM-7351-RES-0402]
R221  0  [SM-7351-RES-0402]
R222  0  [SM-7351-RES-0603]
R223  0  [SM-7351-RES-0402]
R224  49.9  [SM-7351-RES-0402]
R225  49.9  [SM-7351-RES-0402]
R226  49.9  [SM-7351-RES-0402]
R227  49.9  [SM-7351-RES-0402]
R228  4.87K  [SM-7351-RES-0402]
R230  0  [SM-7351-RES-0402]
R231  0  [SM-7351-RES-0402]
R232  2.2K  [sm-7351-res-0402]
R233  10K  [SM-7351-RES-0402]
R234  0  [SM-7351-RES-0402]
R235  2.2K  [sm-7351-res-0402]
R236  2.2K  [sm-7351-res-0402]
R237  2.2K  [sm-7351-res-0402]
R238  2.2K  [sm-7351-res-0402]
U17  TLK105L  [qfn5x5-32-39m]
U71  SN74LVC1G08  [sm-so-sc70-5]
sheet Pg17: Gbit Ethernet #1
C174  0.1uF  [SM-7351-CAP-0402]
C175  10uF  [SM-7351-CAP-0805]
C176  0.1uF  [SM-7351-CAP-0402]
C177  10uF  [SM-7351-CAP-0805]
C178  47uF  [SM-7351-CAP-1206]
C179  47uF  [SM-7351-CAP-1206]
C180  10uF  [SM-7351-CAP-0805]
C181  0.1uF  [SM-7351-CAP-0402]
C182  10uF  [SM-7351-CAP-0805]
C183  0.1uF  [SM-7351-CAP-0402]
C184  10uF  [SM-7351-CAP-0805]
C185  0.1uF  [SM-7351-CAP-0402]
C186  0.01uF  [SM-7351-CAP-0402]
C187  0.1uF  [SM-7351-CAP-0402]
C188  0.1uF  [SM-7351-CAP-0402]
C189  10uF  [SM-7351-CAP-0805]
C190  0.01uF  [SM-7351-CAP-0402]
C191  0.01uF  [SM-7351-CAP-0402]
C192  0.01uF  [SM-7351-CAP-0402]
C193  18pF  [SM-7351-CAP-0402]
C194  18pF  [SM-7351-CAP-0402]
D4  MMSD103T1  [sod-123]
FB5  600mAFB10ohm  [HF70ACB201209]
FB6  600mAFB10ohm  [HF70ACB201209]
FB7  600mAFB10ohm  [HF70ACB201209]
FB8  600mAFB10ohm  [HF70ACB201209]
J12  RJ-45 Gigabit  [CNRJ45-1X1WLED-598M]
Q8  FDT434P  [SOT223-4]
R322  0  [SM-7351-RES-0603]
R324  100K  [SM-7351-RES-0402]
R325  22  [SM-7351-RES-0402]
R326  22  [SM-7351-RES-0402]
R327  22  [SM-7351-RES-0402]
R328  22  [SM-7351-RES-0402]
R329  22  [SM-7351-RES-0402]
R330  22  [SM-7351-RES-0402]
R331  22  [SM-7351-RES-0402]
R332  22  [SM-7351-RES-0402]
R333  22  [SM-7351-RES-0402]
R334  22  [SM-7351-RES-0402]
R335  22  [SM-7351-RES-0402]
R336  22  [SM-7351-RES-0402]
R337  220  [SM-7351-RES-0402]
R338  0  [SM-7351-RES-0402]
R339  0  [SM-7351-RES-0402]
R340  220  [SM-7351-RES-0402]
R341  12.1K, 1%  [SM-7351-RES-0402]
R342  4.7K  [SM-7351-RES-0402]
R343  10K  [SM-7351-RES-0402]
R345  10K  [SM-7351-RES-0402]
R348  1K  [SM-7351-RES-0402]
R349  1M  [SM-7351-RES-0402]
R351  0  [SM-7351-RES-0402]
R352  10K  [SM-7351-RES-0402]
R353  10K  [SM-7351-RES-0402]
R354  33  [SM-7351-RES-0402]
R356  DNI  [SM-7351-RES-0402]
R357  33  [SM-7351-RES-0402]
R358  DNI  [SM-7351-RES-0402]
R359  33  [SM-7351-RES-0402]
R361  1K  [SM-7351-RES-0402]
R363  1K  [SM-7351-RES-0402]
R364  10K  [SM-7351-RES-0402]
TP17  TP1mm  [tp_smd1mmcircle]
U24  KSZ9031RN  [qfn7x7-48]
U25  CDCE913  [TSSOP5X4-14-47M]
U26  SN74LVC1G07  [SC70-5-43M]
Y4  25MHz  [SM_OSC_ABM3]
sheet Pg18: SDMMC #1 Interface
C211  0.1uF  [SM-7351-CAP-0402]
C212  4.7uF  [SM-7351-CAP-0603]
J15  SCHA5B0200  [SD-MICRO-SCHA5B0300]
J44  DNI HEADER 2  [header_2x1]
R397  10K  [SM-7351-RES-0402]
R398  10K  [SM-7351-RES-0402]
R399  10K  [SM-7351-RES-0402]
R400  10K  [SM-7351-RES-0402]
R401  10K  [SM-7351-RES-0402]
R402  0  [SM-7351-RES-0402]
R403  0  [SM-7351-RES-0402]
R404  0  [SM-7351-RES-0402]
R405  0  [SM-7351-RES-0402]
R406  0  [SM-7351-RES-0402]
R407  0  [SM-7351-RES-0402]
R408  470K  [SM-7351-RES-0402]
R409  0  [SM-7351-RES-0402]
R644  10K  [SM-7351-RES-0402]
U30  TPD6E001  [U_10_RSE]
U84  TPD1E10B06  [tpd1e10b06-2l]
sheet Pg30: PCIE Connector
C303  0.1uF  [SM-7351-CAP-0402]
C304  0.1uF  [SM-7351-CAP-0402]
C305  10uF  [SM-7351-CAP-0805]
C306  10uF  [SM-7351-CAP-0805]
C307  10uF  [SM-7351-CAP-0805]
C308  0.01uF  [SM-7351-CAP-0402]
C309  0.01uF  [SM-7351-CAP-0402]
C310  0.01uF  [SM-7351-CAP-0402]
C320  10uF  [SM-7351-CAP-0805]
C321  0.01uF  [SM-7351-CAP-0402]
C322  0.01uF  [SM-7351-CAP-0402]
C324  0.01uF  [SM-7351-CAP-0402]
C326  0.01uF  [SM-7351-CAP-0402]
C436  0.1uF  [SM-7351-CAP-0402]
C437  0.1uF  [SM-7351-CAP-0402]
C438  0.1uF  [SM-7351-CAP-0402]
C439  0.1uF  [SM-7351-CAP-0402]
C469  0.01uF  [SM-7351-CAP-0402]
C470  0.01uF  [SM-7351-CAP-0402]
C477  0.1uF  [SM-7351-CAP-0402]
C478  0.1uF  [SM-7351-CAP-0402]
C581  0.1uF  [SM-7351-CAP-0402]
C582  0.1uF  [SM-7351-CAP-0402]
FB13  150OHM800mA  [sm-7351-ind-0805]
J49  HEADER 2  [header_2x1]
J52  10061913  [CNPCIE64SMT]
L3  NFM21PC474  [FILT-NFM21PC]
M1  Shunt0.1in  [none]
R539  10K  [SM-7351-RES-0402]
R542  10K  [SM-7351-RES-0402]
R543  10K  [SM-7351-RES-0402]
R544  10K  [SM-7351-RES-0402]
R545  10K  [SM-7351-RES-0402]
R546  10K  [SM-7351-RES-0402]
R547  DNI  [SM-7351-RES-0402]
R548  10K  [SM-7351-RES-0402]
R549  10K  [SM-7351-RES-0402]
R550  0  [SM-7351-RES-0402]
R568  0  [SM-7351-RES-0402]
R580  100  [SM-7351-RES-0402]
R581  100  [SM-7351-RES-0402]
R649  10K  [SM-7351-RES-0402]
R650  100  [SM-7351-RES-0402]
R652  0  [SM-7351-RES-0402]
R653  0  [SM-7351-RES-0402]
R654  10K  [SM-7351-RES-0402]
R655  100  [SM-7351-RES-0402]
TP20  TP1mm  [tp_smd1mmcircle]
U44  74LVC1G125  [SC70-5-43M]
U45  CDCM9102  [qfn5x5-32ti-39m]
U85  SN74LVC1G08  [sm-so-sc70-5]
Y7  25MHz  [asf_smd3_2x5mm]
sheet Pg32: Expansion Connector
U1  AM5718AABCXEA  [BGA23X23-760-117M]  (sections -1,-10,-11,-12,-13,-14,-15,-16,-17,-18,-19,-2,-20,-21,-22,-23,-24,-25,-26,-27,-3,-4,-5,-6,-7,-8,-9)

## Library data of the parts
C268-C271 C276-C280 = 1C_47uFCapacitor10V20%SMD1206
C212 C272-C275 C281-C285 C416 = 1C_4.7uFCapacitor16V10%0603
C415 = 1C_0.1uFCapacitor16V10%0402: Installed: DNI
C102-C104 C107-C109 C111 C116 C117 C119 C122-C124 C126 C128 C129 C132-C135 C138 C140 C141 C143 C145 C147 C148 C150 C174 C176 C181 C183 C185 C211 C417 C436-C439 C460 C477 C478 C581 C582 = 1C_0.1uFCapacitor16V10%0402
C418 C419 = 1C_22uFCapacitor16V10%0805
C110 C125 C136 C149 C175 C177 C180 C182 C184 C189 C305-C307 C320 C458 = 1C_10uFCapacitor16V10%0805
C459 = 1C_1uFCapacitor50V10%0603
C461 C462 = 1C_10uFCapacitor35V10%0805
C463 = 1C_1.1nFCapacitor50V5%0603
C471 C472 = 1C_2.2uF16V10%SMD0805
C476 = 1C_2.2uFCapacitor10V20%smd0402
D20 = 1E_Diode_1ARect_Rev20V: TIIntPartnumber: _1E0027
L12 = 1L_0.5Alowprof_5
L13 = 1L_0.5Alowprof_4
L14 = 1L_0.5Alowprof_8
L15 = 1L_0.5Alowprof_3
L16 = 1L_0.5Alowprof_2
L17 = 1L_0.5Alowprof_1
L18 = 1L_0.5Alowprof_7
L19 = 1L_0.5Alowprof
L20 = 1L_0.5Alowprof_6
L22 = 1L_0.1Asmd
L28 = 1L_0.5Asmd
R324 R419 = 1R_100KOhmResistor1_16W0402
R424 = 1R_1.62MOhmResistor1_16W0402
R427 = 1R_180KOhmResistor1_16W0402
R646 = 1R_51Kohm1_16W1%smd0402
R647 = 1R_158Kohm1_16W1%smd0402
R648 = 1R_18.2Kohm1_16W1%smd0402
R97 R138 R141 R180 R218 R222 R322 R656 R742 = 1R_ZeroOhmResistor1_16W0603
R77-R96 R98 R106 R112 R115 R117-R119 R121-R130 R132-R137 R139 R140 R142 R148 R151 R154 R160-R179 R181 R188 R189 R195-R199 R202-R217 R219-R221 R223 R230 R231 R234 R338 R339 R351 R356 R358 R402-R407 R409 R547 R550 R568 R652 R653 R678 R679 = 1R_ZeroOhmResistor1_16W0402
R680 = 1R_10KOhmResistor1_10W1%0402
R681 = 1R_19.6KohmResistor1_16W1%0402
TP26 = 2H_TestPointThroughHole
U3 = 1A_TPS659040_Indus_2
U62 = 1A_TPS63010YFF
U79 = 1A_TPS61085
U86 = 1A_LP38693ADJ: MfrNum: LP38693MP-ADJ/NOPB
C105 C112 C113 C118 C120 C127 C130 C137 C139 C142 C144 C151 C186 C190-C192 C308-C310 C321 C322 C324 C326 C469 C470 = 1C_0.01uFCapacitor16V10%0402
C106 C121 C131 C146 = 1C_4700pFCapacitor50V10%0402
J3 J5 J6 J8 = 2J_ConnectorRJ45_10_100MbAMDIX
R76 R104 R108-R111 R120 R131 R152 R155-R159 R187 R191-R194 R200 R201 R232 R235-R238 = 1R_2.2KOhmResistor1_16W0402
R99-R102 R143-R146 R182-R185 R224-R227 = 1R_49.9OhmResistor1_16W0402
R103 R147 R186 R228 = 1R_4.87Kohm1_16W1%smd0402
R107 R153 R190 R233 R343 R345 R352 R353 R364 R397-R401 R539 R542-R546 R548 R549 R644 R649 R654 = 1R_10KOhmResistor1_16W0402
U9 U13 U15 U17 = 1A_TLK105L
U68-U71 U85 = 1A_SN74LVC1G08DCKT_SC70
J4 J7 = 2H_Header_5x1
C178 C179 = 1C_47uFCapacitor16V20%1206
C187 C188 C303 C304 = 1C_0.1uFCapacitor50V10%0402
C193 C194 = 1C_18pFCapacitor16V10%0402
D4 = Diode200mA250V_0: TIIntPartnumber: _1E0013
FB5 = 1L_FerriteBead_0_3
FB6 = 1L_FerriteBead_0_2
FB7 = 1L_FerriteBead_0
FB8 = 1L_FerriteBead_0_1
J12 = 2J_ConnectorRJ45_Gigabit
Q8 = 1Q_MOSFET_PChan_FDT434P
R325-R336 = 1R_22OhmResistor1_16W1%0402
R337 R340 = 1R_220ohm1_10W1%smd0402
R341 = 1R_12.1KohmResistor1_16W1%0402
R342 = 1R_4.7KOhmResistor1_16W0402
R348 R361 R363 = 1R_1KOhmResistor1_16W0402
R349 = 1MOhmResistor1_16W0402
R354 R357 R359 = 1R_33ohmResistor1_16W5%0402
TP17 TP20 = 2H_Testpoint_SMD1mmCircle
U24 = 1A_KSZ9031RNX
U25 = 1A_CDCE913
U26 = 1A_SN74LVC1G07
Y4 = 1Y_Crystal25MHzABM3_1
J15 = 2C_Conn_microSD_8
J44 J49 = 2H_Header_0
R408 = 470Kohm1_16W1%SMD0402
U30 = 1A_TPD6E001RSE
U84 = 1A_TPD1E10B06_0
FB13 = 1L_FerBead_0
J52 = 2C_PCIEConnector_x4SMT_10061913: DescriptiveText: PCIE Connector Card Edge Type 64pin; MfrNum: 10061913-101TLF; PartName: PCIE_Connector64pin
L3 = 1L_NFM21PC474_EMIFilter
M1 = 2H_Shunt0.1in
R580 R581 R650 R655 = 1R_100ohm1_16W1%SMD0402
U44 = 1A_SN74LVC1G125
U45 = 1A_CDCM9102
Y7 = 1Y_Oscillator25MHzSMD
U1 = AM571X_ABCpkg_Industrial_11

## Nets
AGND_GBETH1: C187.2 C188.2 J12.SHLD1 J12.SHLD2
AGNDFRAME_PRU1ETH0: C106.2 J3.SHLD1 J3.SHLD2
AGNDFRAME_PRU1ETH1: C121.2 J5.SHLD1 J5.SHLD2
AGNDFRAME_PRU2ETH0: C131.2 J6.SHLD1 J6.SHLD2
AGNDFRAME_PRU2ETH1: C146.2 J8.SHLD1 J8.SHLD2
DGND: C102.2 C103.2 C104.2 C105.2 C106.1 C107.2 C108.2 C109.2 C110.2 C111.2 C112.2 C113.2 C116.2 C117.2 C118.2 C119.2 C120.2 C121.1 C122.2 C123.2 C124.2 C125.2 C126.2 C127.2 C128.2 C129.2 C130.2 C131.1 C132.2 C133.2 C134.2 C135.2 C136.2 C137.2 C138.2 C139.2 C140.2 C141.2 C142.2 C143.2 C144.2 C145.2 C146.1 C147.2 C148.2 C149.2 C150.2 C151.2 C174.2 C175.2 C176.2 C177.2 C178.2 C179.2 C180.2 C181.2 C182.2 C183.2 C184.2 C185.2 C186.2 C187.1 C188.1 C189.2 C190.2 C191.2 C192.2 C193.1 C194.1 C211.2 C212.2 C268.2 C269.2 C270.2 C271.2 C272.2 C273.2 C274.2 C275.2 C276.2 C277.2 C278.2 C279.2 C280.2 C281.2 C282.2 C283.2 C284.2 C285.2 C303.2 C304.2 C305.2 C306.2 C307.2 C308.2 C309.2 C310.2 C320.2 C321.2 C322.2 C324.2 C326.2 C415.2 C416.2 C417.2 C418.2 C419.2 C458.2 C459.2 C460.2 C461.2 C462.2 C463.2 C469.2 C470.2 C471.2 C472.2 C476.2 J3.8 J4.5 J5.8 J6.8 J7.5 J8.8 J12.1 J12.12 J12.13 J15.6(VSS) J15.9(GND) J15.11(GND3) J15.12(GND4) J15.13(GND5) J15.14(GND6) J15.15(GND7) J15.16(GND8) J44.2 J52.A4 J52.A12 J52.A15 J52.A18 J52.A20 J52.A23 J52.A24 J52.A27 J52.A28 J52.A31 J52.B4 J52.B7 J52.B13 J52.B16 J52.B18 J52.B21 J52.B22 J52.B25 J52.B26 J52.B29 J52.B31 J52.B32 L3.2(GND) R103.1(P1) R104.1(P1) R108.1(P1) R109.1(P1) R110.1(P1) R111.1(P1) R147.1(P1) R155.1(P1) R156.1(P1) R157.1(P1) R158.1(P1) R186.1(P1) R187.1(P1) R191.1(P1) R192.1(P1) R193.1(P1) R194.1(P1) R228.1(P1) R235.1(P1) R236.1(P1) R237.1(P1) R238.1(P1) R341.2 R348.1(P1) R361.1(P1) R363.1(P1) R427.1(P1) R539.2(P2) R542.1(P1) R547.2(P2) R550.2(P2) R648.1(P1) R680.1 U3.C12(SMPS12_FBK_GND) U3.D4(SMPS7_GND) U3.D5(SMPS7_GND) U3.D10(SMPS1_GND) U3.E4(SMPS7_GND) U3.E9(SMPS1_GND) U3.E10(SMPS1_GND) U3.F4(SMPS4_GND) U3.F9(SMPS2_GND) U3.F10(SMPS2_GND) U3.G4(SMPS4_GND) U3.G5(SMPS4_GND) U3.G10(SMPS2_GND) U3.H4(SMPS5_GND) U3.H5(SMPS5_GND) U3.H10(SMPS3_GND) U3.J4(SMPS5_GND) U3.J9(SMPS3_GND) U3.J10(SMPS3_GND) U3.K3(SMPS45_FDBK_GND) U3.L5(SMPS6_GND) U3.L6(SMPS6_GND) U3.L7(SMPS9_GND) U3.L8(SMPS9_GND) U3.L9(SMPS8_GND) U3.L10(SMPS8_GND) U9.TPAD U13.TPAD U15.TPAD U17.TPAD U24.13(VSS_PS) U24.29(VSS) U24.49(P_GND) U25.5(GND1) U25.10(GND2) U26.3(GND) U30.5(GND) U44.3(GND) U45.14(GND) U45.22(GND) U45.TPAD(PWRPAD) U62.B4(SYNC) U62.C1(PGND) U62.C2(PGND) U62.C3(GND) U62.D3(GND) U62.E4(GND) U68.3(GND) U69.3(GND) U70.3(GND) U71.3(GND) U79.4(GND) U84.2 U85.3(GND) U86.5(GND) Y7.2(GND) ; also on sheet 1 2 3 4 5 6 7 8 9 10 11 12 14 15 16 17 18 27 28 29 30 31 32
V1_8D: C190.1 U25.3(VDD) ; also on sheet 4 9 17 27 31
V3_3ACDCM: C320.1 C321.1 C322.1 C324.1 L3.3(OUT) U45.1(VDD2_OUT1) U45.4(VDD1_OUT0)
V3_3APCIE: C307.1 C308.1 C309.1 C310.1 C326.1 FB13.1 R546.2(P2) R548.2(P2) R549.2(P2) U45.9(VDD) U45.16(VDD) U45.18(VDD) U45.20(VDD) Y7.4(VCC)
V3_3AUX_PCIE: J49.2 J52.B10 R654.2(P2)
V3_3D: C104.1 C105.1 C107.1 C113.1 C119.1 C120.1 C122.1 C127.1 C130.1 C132.1 C133.1 C139.1 C143.1 C144.1 C145.1 C151.1 C191.1 C211.1 C212.1 C469.1 C470.1 FB5.1 FB13.2 J15.4(VDD) J49.1 J52.A9 J52.A10 J52.B8 L3.1(IN) R76.2(P2) R77.2(P2) R78.2(P2) R89.2(P2) R97.1(P1) R99.1(P1) R100.1(P1) R101.1(P1) R102.1(P1) R107.2(P2) R120.2(P2) R121.2(P2) R122.2(P2) R131.2(P2) R134.2(P2) R141.1(P1) R143.1(P1) R144.1(P1) R145.1(P1) R146.1(P1) R152.2(P2) R153.2(P2) R159.2(P2) R160.2(P2) R161.2(P2) R172.2(P2) R180.1(P1) R182.1(P1) R183.1(P1) R184.1(P1) R185.1(P1) R190.2(P2) R200.2(P2) R201.2(P2) R202.2(P2) R203.2(P2) R214.2(P2) R222.1(P1) R224.1(P1) R225.1(P1) R226.1(P1) R227.1(P1) R232.2(P2) R233.2(P2) R322.2(P2) R419.2(P2) R543.1(P1) R544.1(P1) R545.2(P2) R649.2(P2) R678.2(P2) R679.2(P2) R742.1(P1) U3.J8(SMPS9_FBK) U9.21(VDD33_IO) U13.21(VDD33_IO) U15.21(VDD33_IO) U17.21(VDD33_IO) U25.6(VDDOUT1) U25.7(VDDOUT2) U30.10(VCC) U44.5(VCC) U68.5(VCC) U69.5(VCC) U70.5(VCC) U71.5(VCC) U85.5(VCC) ; also on sheet 1 2 3 4 5 6 7 8 9 10 11 12 14 15 17 18 27 28 29 30 31 32
V3_3D_PRU1ETH0JCK: C102.1 C103.1 J3.3 J3.4 R77.1(P1)
V3_3D_PRU1ETH1JCK: C116.1 C117.1 J5.3 J5.4 R121.1(P1)
V3_3D_PRU2ETH0JCK: C128.1 C129.1 J6.3 J6.4 R160.1(P1)
V3_3D_PRU2ETH1JCK: C140.1 C141.1 J8.3 J8.4 R202.1(P1)
V3_7LCD: C472.1 R681.1 U86.3(VOUT) ; also on sheet 4
V5_0D: C418.1 C419.1 C476.1 R424.2(P2) U62.E1(VOUT) U62.E2(VOUT) ; also on sheet 5 14 15 18 29
V5_0D_EN: R419.1(P1) U62.A4(EN)
V5_0DFB: R424.1(P1) R427.2(P2) U62.E3(FB)
V12_0D: C303.1 C304.1 C461.1 C462.1 D20.1(CATHODE) J52.A2 J52.A3 J52.B1 J52.B2 J52.B3 R647.2(P2) ; also on sheet 18
VDD_CORE: U3.B1(SMPS7_FDBK) ; also on sheet 17 31
VDD_GPU: C268.1 L17.2 U3.K6(SMPS6_FBK) ; also on sheet 17 31
VDD_IVA: U3.K2(SMPS45_FDBK) ; also on sheet 17 31
VDD_MPU: U3.B13(SMPS12_FBK) ; also on sheet 17 31
VDDS_DDR: R656.1(P1) ; also on sheet 8 16 17
AM57XX_MMC1_CLK: R405.2(P2) U1.W6(MMC1_CLK)
AM57XX_MMC1_CMD: R404.2(P2) U1.Y6(MMC1_CMD)
AM57XX_MMC1_DAT0: R406.2(P2) U1.AA6(MMC1_DAT0)
AM57XX_MMC1_DAT1: R407.2(P2) U1.Y4(MMC1_DAT1)
AM57XX_MMC1_DAT2: R402.2(P2) U1.AA5(MMC1_DAT2)
AM57XX_MMC1_DAT3: R403.2(P2) U1.Y3(MMC1_DAT3)
AM57XX_MMC1_SDCD: R409.2(P2) U1.W7(MMC1_SDCD)
AM57XX_MMC1_SDWP: J44.1 R644.1(P1) U1.Y9(MMC1_SDWP)
AM57XX_PCIE_PERn0: J52.A17 U1.AG13(PCIE_RXN0)
AM57XX_PCIE_PERn1: J52.A22 U1.AF12(PCIE_RXN1)
AM57XX_PCIE_PERp0: J52.A16 U1.AH13(PCIE_RXP0)
AM57XX_PCIE_PERp1: J52.A21 U1.AE12(PCIE_RXP1)
AM57XX_PCIE_PETn0: C477.1 U1.AG14(PCIE_TXN0)
AM57XX_PCIE_PETn1: C581.1 U1.AC11(PCIE_TXN1)
AM57XX_PCIE_PETp0: C478.1 U1.AH14(PCIE_TXP0)
AM57XX_PCIE_PETp1: C582.1 U1.AD11(PCIE_TXP1)
AM57XX_PCIE_REF_CLKN: C438.2 R581.1(P1) U1.AH15(LJCB_CLKN)
AM57XX_PCIE_REF_CLKP: C439.2 R581.2(P2) U1.AG15(LJCB_CLKP)
AM57XX_PR1_UART0_TXD: R199.2(P2) ; also on sheet 12 29
AM57XX_PRU1ETH1_TXCLK: R123.2(P2) U1.C1(VIN2A_D6/PR1_MII_MT1_CLK)
AM57XX_PRU1ETH1_TXD2: R127.2(P2) U1.E6(VIN2A_D9/PR1_MII1_TXD2)
AM57XX_PRU1ETH1_TXD3: R128.2(P2) U1.F5(VIN2A_D8/PR1_MII1_TXD3)
AM57XX_PRU1ETH1_TXEN: R124.2(P2) U1.E4(VIN2A_D7/PR1_MII1_TXEN)
AM57XX_PRU1ETH_MDCLK: R96.2(P2) R140.2(P2) U1.D3(VIN2A_D10/PR1_MDIO_MDCLK)
AM57XX_PRU1ETH_MDDATA: R98.2(P2) R142.2(P2) U1.F6(VIN2A_D11/PR1_MDIO_DATA)
AM57XX_PRU2ETH0_COL: R178.2(P2) U1.F15(MCASP3_FSX/PR2_MII0_COL) ; also on sheet 29
AM57XX_PRU2ETH0_CRS: R177.2(P2) U1.B18(MCASP3_ACLKX/PR2_MII0_CRS) ; also on sheet 29
AM57XX_PRU2ETH0_MRCLK: R165.2(P2) U1.A13(MCASP1_AXR13/PR2_MII_MR0_CLK)
AM57XX_PRU2ETH0_RXD0: R171.2(P2) U1.C15(MCASP2_AXR2/PR2_MII0_RXD0)
AM57XX_PRU2ETH0_RXD1: R173.2(P2) U1.A18(MCASP2_FSX/PR2_MII0_RXD1)
AM57XX_PRU2ETH0_RXD2: R174.2(P2) U1.A19(MCASP2_ACLKX/PR2_MII0_RXD2)
AM57XX_PRU2ETH0_RXD3: R175.2(P2) U1.F14(MCASP1_AXR15/PR2_MII0_RXD3)
AM57XX_PRU2ETH0_RXDV: R166.2(P2) R197.2(P2) U1.G14(MCASP1_AXR14/PR2_MII0_RXDV)
AM57XX_PRU2ETH0_RXER: R170.2(P2) U1.G12(MCASP1_AXR0/PR2_MII0_RXER)
AM57XX_PRU2ETH0_RXLINK: R188.2(P2) U1.A16(MCASP2_AXR3/PR2_MII0_RXLINK)
AM57XX_PRU2ETH0_TXCLK: R162.2(P2) U1.F12(MCASP1_AXR1/PR2_MII_MT0_CLK)
AM57XX_PRU2ETH0_TXD0: R163.2(P2) U1.E14(MCASP1_AXR12/PR2_MII0_TXD0)
AM57XX_PRU2ETH0_TXD1: R164.2(P2) U1.A12(MCASP1_AXR11/PR2_MII0_TXD1)
AM57XX_PRU2ETH0_TXD2: R168.2(P2) U1.B13(MCASP1_AXR10/PR2_MII0_TXD2)
AM57XX_PRU2ETH0_TXD3: R169.2(P2) U1.A11(MCASP1_AXR9/PR2_MII0_TXD3)
AM57XX_PRU2ETH0_TXEN: R167.2(P2) R196.2(P2) U1.B12(MCASP1_AXR8/PR2_MII0_TXEN)
AM57XX_PRU2ETH1_COL: R220.2(P2) U1.D18(XREF_CLK0/PR2_MII1_COL) ; also on sheet 29
AM57XX_PRU2ETH1_CRS: R219.2(P2) U1.E17(XREF_CLK1/PR2_MII1_CRS) ; also on sheet 29
AM57XX_PRU2ETH1_MRCLK: R209.2(P2) U1.AC9(MMC3_DAT2/PR2_MII_MR1_CLK)
AM57XX_PRU2ETH1_RXD0: R213.2(P2) U1.AB5(MMC3_DAT7/PR2_MII1_RXD0)
AM57XX_PRU2ETH1_RXD1: R215.2(P2) U1.AB8(MMC3_DAT6/PR2_MII1_RXD1)
AM57XX_PRU2ETH1_RXD2: R216.2(P2) U1.AD6(MMC3_DAT5/PR2_MII1_RXD2)
AM57XX_PRU2ETH1_RXD3: R217.2(P2) U1.AC8(MMC3_DAT4/PR2_MII1_RXD3)
AM57XX_PRU2ETH1_RXDV: R211.2(P2) U1.AC3(MMC3_DAT3/PR2_MII1_RXDV)
AM57XX_PRU2ETH1_RXER: R212.2(P2) U1.B19(MCASP3_AXR0/PR2_MII1_RXER)
AM57XX_PRU2ETH1_TXCLK: R204.2(P2) U1.AC5(GPIO6_10/PR2_MII_MT1_CLK)
AM57XX_PRU2ETH1_TXD0: R206.2(P2) U1.AC6(MMC3_DAT1/PR2_MII1_TXD0)
AM57XX_PRU2ETH1_TXD1: R208.2(P2) U1.AC7(MMC3_DAT0/PR2_MII1_TXD1)
AM57XX_PRU2ETH1_TXD2: R210.2(P2) U1.AC4(MMC3_CMD/PR2_MII1_TXD2)
AM57XX_PRU2ETH1_TXD3: R207.2(P2) U1.AD4(MMC3_CLK/PR2_MII1_TXD3)
AM57XX_PRU2ETH1_TXEN: R205.2(P2) U1.AB4(GPIO6_11/PR2_MII1_TXEN)
AM57XX_PRU2ETH_MDCLK: R179.2(P2) R221.2(P2) U1.C14(MCASP1_ACLKX/PR2_MDIO_MDCLK)
AM57XX_PRU2ETH_MDDATA: R181.2(P2) R223.2(P2) U1.D14(MCASP1_FSX/PR2_MDIO_DATA)
AM57XX_RGMII1_RD0: R333.2(P2) U1.A4(VIN2A_D23/RGMII1_RXD0)
AM57XX_RGMII1_RD1: R334.2(P2) U1.B5(VIN2A_D22/RGMII1_RXD1)
AM57XX_RGMII1_RD2: R335.2(P2) U1.B4(VIN2A_D21/RGMII1_RXD2)
AM57XX_RGMII1_RD3: R336.2(P2) U1.B3(VIN2A_D20/RGMII1_RXD3)
AM57XX_RGMII1_RXCLK: R328.2(P2) U1.C5(VIN2A_D18/RGMII1_RXC)
AM57XX_RGMII1_RXCTL: R329.2(P2) U1.A3(VIN2A_D19/RGMII1_RXCTL)
AM57XX_RGMII1_TD0: R330.2(P2) U1.D6(VIN2A_D17/RGMII1_TXD0)
AM57XX_RGMII1_TD1: R331.2(P2) U1.B2(VIN2A_D16/RGMII1_TXD1)
AM57XX_RGMII1_TD2: R327.2(P2) U1.C4(VIN2A_D15/RGMII1_TXD2)
AM57XX_RGMII1_TD3: R332.2(P2) U1.C3(VIN2A_D14/RGMII1_TXD3)
AM57XX_RGMII1_TXCLK: R325.2(P2) U1.D5(VIN2A_D12/RGMII1_TXC)
AM57XX_RGMII1_TXCTL: R326.2(P2) U1.C2(VIN2A_D13/RGMII1_TXCTL)
AM57XX_VIN2A_DE0: R119.2(P2) ; also on sheet 29
AM57XX_VIN2A_HSYNC0: R118.2(P2) ; also on sheet 29
AM571X_PRU1ETH1_COL: R148.2(P2) U1.E2(VIN2A_D3/PR1_MII1_COL) ; also on sheet 29
AM571X_PRU1ETH1_TXD0: R125.2(P2) U1.F4(VIN2A_D5/PR1_MII1_TXD0) ; also on sheet 12 29
AM571X_PRU1ETH1_TXD1: R126.2(P2) U1.D2(VIN2A_D4/PR1_MII1_TXD1) ; also on sheet 29
AM571X_VIN2A_VSYNC0: R198.2(P2) ; also on sheet 29
AM572X_HDMI_DDC_SCL: R358.2(P2) ; also on sheet 5
AM572X_HDMI_DDC_SDA: R356.2(P2) ; also on sheet 5
ETH1_LDO_O: Q8.G(GATE) U24.43(LDO_O)
ETH1_MDC: R338.1(P1) U24.36(MDC)
ETH1_MDIO: R339.1(P1) U24.37(MDIO)
ETH1_RESETn: C189.1 D4.2 R324.1(P1) U24.42(RESET_N) U26.4(Y)
ETH1_RXCLK: R328.1(P1) R361.2(P2) U24.35(RX_CLK)
ETH1_RXD0: R333.1(P1) R343.2(P2) U24.32(RXD0)
ETH1_RXD1: R334.1(P1) R345.2(P2) U24.31(RXD1)
ETH1_RXD2: R335.1(P1) R352.2(P2) U24.28(RXD2)
ETH1_RXD3: R336.1(P1) R353.2(P2) U24.27(RXD3)
ETH1_RXDV: R329.1(P1) R348.2(P2) U24.33(RX_DV)
ETH1_TXCLK: R325.1(P1) U24.24(GTX_CLK)
ETH1_TXD0: R330.1(P1) U24.19(TXD0)
ETH1_TXD1: R331.1(P1) U24.20(TXD1)
ETH1_TXD2: R327.1(P1) U24.21(TXD2)
ETH1_TXD3: R332.1(P1) U24.22(TXD3)
ETH1_TXEN: R326.1(P1) U24.25(TX_EN)
ETH1GB_25MHzCLK: R359.2 U24.46(XI)
ETH_MDIO_CLK: R338.2(P2) ; also on sheet 27 29
ETH_MDIO_DATA: R339.2(P2) ; also on sheet 27 29
ETHER1_D0N: J12.10 U24.3(TXRXM_A)
ETHER1_D0P: J12.9 U24.2(TXRXP_A)
ETHER1_D1N: J12.8 U24.6(TXRXM_B)
ETHER1_D1P: J12.7 U24.5(TXRXP_B)
ETHER1_D2N: J12.6 U24.8(TXRXM_C)
ETHER1_D2P: J12.5 U24.7(TXRXP_C)
ETHER1_D3N: J12.4 U24.11(TXRXM_D)
ETHER1_D3P: J12.3 U24.10(TXRXP_D)
GB_ETH1_INTn: R342.1(P1) U24.38(INT_N_/_PME_N2) ; also on sheet 29
GPIO_PCIE_RSTDRVn: U44.1(~{OE}) ; also on sheet 29
GPIO_PCIE_SWRSTn: U85.2(B) ; also on sheet 29
GPIO_PRU1_ETH_RESETn: R112.2(P2) R154.2(P2) ; also on sheet 29
GPIO_PRU2_ETH_RESETn: R195.2(P2) R234.2(P2) ; also on sheet 29
IND_I2C_SCL: R652.2(P2) ; also on sheet 4 9 10 11 18 27 29
IND_I2C_SDA: R653.2(P2) ; also on sheet 4 9 10 11 18 27 29
MMC_CD: J15.10(CD) R408.1(P1) R409.1(P1) U84.1
MMC_CLK: J15.5(CLOCK) R405.1(P1) U30.1(IO1)
MMC_CMD: J15.3(CMD) R398.1(P1) R404.1(P1) U30.7(IO5)
MMC_D0: J15.7(DAT0) R399.1(P1) R406.1(P1) U30.2(IO2)
MMC_D1: J15.8(DAT1) R400.1(P1) R407.1(P1) U30.3(IO3)
MMC_D2: J15.1(DAT2) R401.1(P1) R402.1(P1) U30.6(IO4)
MMC_D3: J15.2(CD/DAT3) R397.1(P1) R403.1(P1) U30.8(IO6)
PCI_CONN_REFN: C436.1 U45.5(OUT0N)
PCI_CONN_REFP: C437.1 U45.6(OUT0P)
PCIE_CRDPRESENT: R650.1(P1) ; also on sheet 29
PCIE_PERSTn: J52.A11 R545.1(P1) U44.4(Y)
PCIE_REFCLKN: C436.2 J52.A14 R580.2(P2)
PCIE_REFCLKP: C437.2 J52.A13 R580.1(P1)
PCIE_RESETn: R568.2(P2) U85.1(A) ; also on sheet 30
PCIE_SMB_CLK: J52.B5 R652.1(P1)
PCIE_SMB_DATA: J52.B6 R653.1(P1)
PCIE_TCK: J52.A5 R542.2(P2)
PCIE_TDI: J52.A6 R543.2(P2)
PCIE_TDO: J52.A7 TP20.1
PCIE_TMS: J52.A8 R544.2(P2)
PCIE_TRSTn: J52.B9 R539.1(P1)
PCIE_WAKEn: R655.1(P1) ; also on sheet 29
PCIECONN_PETn0: C477.2 J52.B15
PCIECONN_PETn1: C581.2 J52.B20
PCIECONN_PETp0: C478.2 J52.B14
PCIECONN_PETp1: C582.2 J52.B19
PHY1_LED_ACTn: R337.1 R364.2(P2) U24.17(LED1_/_PME_N1)
PHY1_LED_LINKn: R340.1 R363.2(P2) U24.15(LED2)
PHY_RESETn: U26.2(A) U68.2(B) U69.2(B) U70.2(B) U71.2(B) ; also on sheet 27 30
PR1_MII0_COL: R95.2(P2) ; also on sheet 4 29
PR1_MII0_CRS: R94.2(P2) ; also on sheet 4
PR1_MII0_RXD0: R88.2(P2) ; also on sheet 4 29
PR1_MII0_RXD1: R90.2(P2) ; also on sheet 4 29
PR1_MII0_RXD2: R91.2(P2) ; also on sheet 4 29
PR1_MII0_RXD3: R92.2(P2) ; also on sheet 4 29
PR1_MII0_RXDV: R86.2(P2) ; also on sheet 4 29
PR1_MII0_RXER: R87.2(P2) ; also on sheet 4 29
PR1_MII0_RXLINK: R76.1(P1) R93.2(P2) U9.17(LED_LINK) ; also on sheet 4 29
PR1_MII0_TXD0: R81.2(P2) ; also on sheet 4 29
PR1_MII0_TXD1: R84.2(P2) ; also on sheet 4 29
PR1_MII0_TXD2: R85.2(P2) ; also on sheet 4 29
PR1_MII0_TXD3: R82.2(P2) ; also on sheet 4 29
PR1_MII0_TXEN: R80.2(P2) ; also on sheet 4 29
PR1_MII1_CRS: R139.2(P2) ; also on sheet 4 29
PR1_MII1_MR1_CLK: R129.2(P2) ; also on sheet 4 29
PR1_MII1_RXD0: R133.2(P2) ; also on sheet 4 29
PR1_MII1_RXD1: R135.2(P2) ; also on sheet 4 29
PR1_MII1_RXD2: R136.2(P2) ; also on sheet 4 29
PR1_MII1_RXD3: R137.2(P2) ; also on sheet 4 29
PR1_MII1_RXDV: R130.2(P2) ; also on sheet 4 29
PR1_MII1_RXER: R132.2(P2) ; also on sheet 4
PR1_MII1_RXLINK: R131.1(P1) R138.2(P2) U13.17(LED_LINK) ; also on sheet 4
PR1_MII_MR0_CLK: R83.2(P2) ; also on sheet 4 29
PR1_MII_MT0_CLK: R79.2(P2) ; also on sheet 4 29
PRU1ETH0_25MHzCLK: U9.23(XI) ; also on sheet 27
PRU1ETH0_COL: R95.1(P1) R104.2(P2) R106.2(P2) U9.29(COL)
PRU1ETH0_CRS: R94.1(P1) U9.27(CRS)
PRU1ETH0_INTn: U9.8(PWRDNn/INTn) ; also on sheet 29
PRU1ETH0_MDC: R96.1(P1) U9.20(MDC)
PRU1ETH0_MDIO: R98.1(P1) U9.19(MDIO)
PRU1ETH0_RESETn: U9.18(RESET_N) U68.4(Y)
PRU1ETH0_RXCLK: R83.1(P1) U9.25(RX_CLK)
PRU1ETH0_RXD0: R88.1(P1) R111.2(P2) U9.30(RXD_0)
PRU1ETH0_RXD1: R90.1(P1) R110.2(P2) U9.31(RXD_1)
PRU1ETH0_RXD2: R91.1(P1) R109.2(P2) U9.32(RXD_2)
PRU1ETH0_RXD3: R92.1(P1) R108.2(P2) U9.1(RXD_3)
PRU1ETH0_RXDV: R86.1(P1) U9.26(RX_DV)
PRU1ETH0_RXERR: R87.1(P1) U9.28(RX_ERR)
PRU1ETH0_TXCLK: R79.1(P1) U9.2(TX_CLK)
PRU1ETH0_TXD0: R81.1(P1) U9.4(TXD_0)
PRU1ETH0_TXD1: R84.1(P1) U9.5(TXD_1)
PRU1ETH0_TXD2: R85.1(P1) U9.6(TXD_2)
PRU1ETH0_TXD3: R82.1(P1) U9.7(TXD_3)
PRU1ETH0_TXEN: R80.1(P1) U9.3(TX_EN)
PRU1ETH1_25MHzCLK: U13.23(XI) ; also on sheet 27
PRU1ETH1_COL: R148.1(P1) R151.2(P2) R152.1(P1) U13.29(COL)
PRU1ETH1_CRS: R139.1(P1) U13.27(CRS)
PRU1ETH1_INTn: U13.8(PWRDNn/INTn) ; also on sheet 29
PRU1ETH1_MDC: R140.1(P1) U13.20(MDC)
PRU1ETH1_MDIO: R120.1(P1) R142.1(P1) U13.19(MDIO)
PRU1ETH1_RESETn: U13.18(RESET_N) U69.4(Y)
PRU1ETH1_RXCLK: R129.1(P1) U13.25(RX_CLK)
PRU1ETH1_RXD0: R133.1(P1) R158.2(P2) U13.30(RXD_0)
PRU1ETH1_RXD1: R135.1(P1) R157.2(P2) U13.31(RXD_1)
PRU1ETH1_RXD2: R136.1(P1) R156.2(P2) U13.32(RXD_2)
PRU1ETH1_RXD3: R137.1(P1) R155.2(P2) U13.1(RXD_3)
PRU1ETH1_RXDV: R130.1(P1) U13.26(RX_DV)
PRU1ETH1_RXERR: R132.1(P1) U13.28(RX_ERR)
PRU1ETH1_TXCLK: R123.1(P1) U13.2(TX_CLK)
PRU1ETH1_TXD0: R125.1(P1) U13.4(TXD_0)
PRU1ETH1_TXD1: R126.1(P1) U13.5(TXD_1)
PRU1ETH1_TXD2: R127.1(P1) U13.6(TXD_2)
PRU1ETH1_TXD3: R128.1(P1) U13.7(TXD_3)
PRU1ETH1_TXEN: R124.1(P1) U13.3(TX_EN)
PRU1ETHER0_RDN: J3.2 R99.2(P2) U9.9(RD-)
PRU1ETHER0_RDP: J3.1 R100.2(P2) U9.10(RD+)
PRU1ETHER0_TDN: J3.6 R101.2(P2) U9.11(TD-)
PRU1ETHER0_TDP: J3.5 R102.2(P2) U9.12(TD+)
PRU1ETHER1_RDN: J5.6 R143.2(P2) U13.9(RD-)
PRU1ETHER1_RDP: J5.5 R144.2(P2) U13.10(RD+)
PRU1ETHER1_TDN: J5.2 R145.2(P2) U13.11(TD-)
PRU1ETHER1_TDP: J5.1 R146.2(P2) U13.12(TD+)
PRU2ETH0_25MHzCLK: R354.2 U15.23(XI)
PRU2ETH0_COL: R178.1(P1) R187.2(P2) R188.1(P1) R189.2(P2) U15.29(COL)
PRU2ETH0_CRS: R177.1(P1) U15.27(CRS)
PRU2ETH0_INTn: U15.8(PWRDNn/INTn) ; also on sheet 29
PRU2ETH0_LINKLED: R159.1(P1) R176.2(P2) U15.17(LED_LINK)
PRU2ETH0_MDC: R179.1(P1) U15.20(MDC)
PRU2ETH0_MDIO: R181.1(P1) U15.19(MDIO)
PRU2ETH0_RESETn: U15.18(RESET_N) U70.4(Y)
PRU2ETH0_RXCLK: R165.1(P1) U15.25(RX_CLK)
PRU2ETH0_RXD0: R171.1(P1) R194.2(P2) U15.30(RXD_0)
PRU2ETH0_RXD1: R173.1(P1) R193.2(P2) U15.31(RXD_1)
PRU2ETH0_RXD2: R174.1(P1) R192.2(P2) U15.32(RXD_2)
PRU2ETH0_RXD3: R175.1(P1) R191.2(P2) U15.1(RXD_3)
PRU2ETH0_RXDV: R166.1(P1) U15.26(RX_DV)
PRU2ETH0_RXERR: R170.1(P1) U15.28(RX_ERR)
PRU2ETH0_TXCLK: R162.1(P1) U15.2(TX_CLK)
PRU2ETH0_TXD0: R163.1(P1) U15.4(TXD_0)
PRU2ETH0_TXD1: R164.1(P1) U15.5(TXD_1)
PRU2ETH0_TXD2: R168.1(P1) U15.6(TXD_2)
PRU2ETH0_TXD3: R169.1(P1) U15.7(TXD_3)
PRU2ETH0_TXEN: R167.1(P1) U15.3(TX_EN)
PRU2ETH1_25MHzCLK: R357.2 U17.23(XI)
PRU2ETH1_COL: R220.1(P1) R231.1(P1) R232.1(P1) U17.29(COL)
PRU2ETH1_CRS: R219.1(P1) U17.27(CRS)
PRU2ETH1_INTn: U17.8(PWRDNn/INTn) ; also on sheet 29
PRU2ETH1_LINKLED: R200.1(P1) R218.2(P2) U17.17(LED_LINK)
PRU2ETH1_MDC: R221.1(P1) U17.20(MDC)
PRU2ETH1_MDIO: R201.1(P1) R223.1(P1) U17.19(MDIO)
PRU2ETH1_RESETn: U17.18(RESET_N) U71.4(Y)
PRU2ETH1_RXCLK: R209.1(P1) U17.25(RX_CLK)
PRU2ETH1_RXD0: R213.1(P1) R238.2(P2) U17.30(RXD_0)
PRU2ETH1_RXD1: R215.1(P1) R237.2(P2) U17.31(RXD_1)
PRU2ETH1_RXD2: R216.1(P1) R236.2(P2) U17.32(RXD_2)
PRU2ETH1_RXD3: R217.1(P1) R235.2(P2) U17.1(RXD_3)
PRU2ETH1_RXDV: R117.2(P2) R211.1(P1) U17.26(RX_DV)
PRU2ETH1_RXERR: R212.1(P1) U17.28(RX_ERR)
PRU2ETH1_TXCLK: R204.1(P1) U17.2(TX_CLK)
PRU2ETH1_TXD0: R206.1(P1) U17.4(TXD_0)
PRU2ETH1_TXD1: R208.1(P1) U17.5(TXD_1)
PRU2ETH1_TXD2: R210.1(P1) U17.6(TXD_2)
PRU2ETH1_TXD3: R207.1(P1) U17.7(TXD_3)
PRU2ETH1_TXEN: R115.2(P2) R205.1(P1) U17.3(TX_EN)
PRU2ETHER0_RDN: J6.2 R182.2(P2) U15.9(RD-)
PRU2ETHER0_RDP: J6.1 R183.2(P2) U15.10(RD+)
PRU2ETHER0_TDN: J6.6 R184.2(P2) U15.11(TD-)
PRU2ETHER0_TDP: J6.5 R185.2(P2) U15.12(TD+)
PRU2ETHER1_RDN: J8.6 R224.2(P2) U17.9(RD-)
PRU2ETHER1_RDP: J8.5 R225.2(P2) U17.10(RD+)
PRU2ETHER1_TDN: J8.2 R226.2(P2) U17.11(TD-)
PRU2ETHER1_TDP: J8.1 R227.2(P2) U17.12(TD+)
RT2_MII0_EDIO_DATA0: J7.3 R198.1(P1)
RT2_MII0_EDIO_DATA1: J7.4 R199.1(P1)
RT2_MII0_RXDV: J7.2 R197.1(P1)
RT2_MII0_TXEN: J7.1 R196.1(P1)
RT2_MII1_EDIO_DATA0: J4.3 R118.1(P1)
RT2_MII1_EDIO_DATA1: J4.4 R119.1(P1)
RT2_MII1_RXDV: J4.2 R117.1(P1)
RT2_MII1_TXEN: J4.1 R115.1(P1)
SERDES_REF_CLKN: C438.1 U45.2(OUT1N)
SERDES_REF_CLKP: C439.1 U45.3(OUT1P)
VADD33_PRU1ETH0: C112.1 R97.2(P2) U9.14(AVDD33)
VADD33_PRU1ETH1: C118.1 R141.2(P2) U13.14(AVDD33)
VADD33_PRU2ETH0: C137.1 R180.2(P2) U15.14(AVDD33)
VADD33_PRU2ETH1: C142.1 R222.2(P2) U17.14(AVDD33)
VAM572X_DDR1: U3.K13(SMPS3_FDBK) ; also on sheet 17
VETH1_AVDDH: C176.1 C177.1 C178.1 FB5.2 Q8.S(SOURCE) U24.1(AVDDH) U24.12(AVDDH) U24.47(AVDDH)
VETH1_AVDDL: C182.1 C183.1 FB8.2 U24.4(AVDDL) U24.9(AVDDL)
VETH1_AVDDL_PLL: C184.1 C185.1 C186.1 FB6.2 U24.44(AVDDL_PLL)
VETH1_AVDDL_PMOS: C179.1 FB6.1 FB7.1 FB8.1 Q8.D1(DRAIN1) Q8.D2(DRAIN2)
VETH1_DVDDH: C174.1 C175.1 C192.1 D4.1 R322.1(P1) R324.2(P2) R342.2(P2) R343.1(P1) R345.1(P1) R352.1(P1) R353.1(P1) R364.1(P1) U24.16(DVDDH) U24.34(DVDDH) U24.40(DVDDH) U26.5(VCC)
VETH1_DVDDL: C180.1 C181.1 FB7.2 U24.14(DVDDL) U24.18(DVDDL) U24.23(DVDDL) U24.26(DVDDL) U24.30(DVDDL) U24.39(DVDDL)
VMAIN: C272.1 C273.1 C274.1 C275.1 C281.1 C282.1 C283.1 C284.1 C285.1 C415.1 C416.1 C458.1 C459.1 C471.1 L28.1 U3.D11(SMPS1_IN_1) U3.D12(SMPS1_IN_2) U3.D13(SMPS1_IN_3) U3.E1(SMPS7_IN_B1_1) U3.E2(SMPS7_IN_B1_2) U3.E3(SMPS7_IN_B1_3) U3.F1(SMPS4_IN1) U3.F2(SMPS4_IN2) U3.F3(SMPS4_IN3) U3.G11(SMPS2_IN_1) U3.G12(SMPS2_IN_2) U3.G13(SMPS2_IN_3) U3.H11(SMPS3_IN1) U3.H12(SMPS3_IN2) U3.H13(SMPS3_IN3) U3.J1(SMPS5_IN1) U3.J2(SMPS5_IN2) U3.J3(SMPS5_IN3) U3.M6(SMPS6_IN) U3.M8(SMPS9_IN) U3.M9(SMPS8_IN) U3.N6(SMPS6_IN) U3.N8(SMPS9_IN) U3.N9(SMPS8_IN) U62.A1(VIN) U62.A2(VIN) U79.6(IN) U79.7(FREQ) U86.4(VIN) ; also on sheet 4 9 11 29
VSDMMC: R397.2(P2) R398.2(P2) R399.2(P2) R400.2(P2) R401.2(P2) R408.2(P2) R644.2(P2) ; also on sheet 9 17 31
VSMPS1_2: C276.1 C277.1 L12.2 L13.2 ; also on sheet 17
VSMPS1_SW: L12.1 U3.E11(SMPS1_SW_1) U3.E12(SMPS1_SW_2) U3.E13(SMPS1_SW_3)
VSMPS2_SW: L13.1 U3.F11(SMPS2_SW1) U3.F12(SMPS2_SW2) U3.F13(SMPS2_SW3)
VSMPS3: C278.1 L14.2 R656.2(P2)
VSMPS3_SW: L14.1 U3.J11(SMPS3_SW1) U3.J12(SMPS3_SW2) U3.J13(SMPS3_SW3)
VSMPS4_5: C279.1 C280.1 L15.2 L16.2 ; also on sheet 17
VSMPS4_SW: L15.1 U3.G1(SMPS4_SW1) U3.G2(SMPS4_SW2) U3.G3(SMPS4_SW3)
VSMPS5_SW: L16.1 U3.H1(SMPS5_SW1) U3.H2(SMPS5_SW2) U3.H3(SMPS5_SW3)
VSMPS6_SW: L17.1 U3.M5(SMPS6_SW) U3.N5(SMPS6_SW)
VSMPS7: C269.1 L18.2 ; also on sheet 17
VSMPS7_SW: L18.1 U3.D1(SMPS7_SW1) U3.D2(SMPS7_SW2) U3.D3(SMPS7_SW3)
VSMPS8: C270.1 L19.2 TP26.1 U3.L11(SMPS8_FDBK)
VSMPS8_SW: L19.1 U3.M10(SMPS8_SW) U3.N10(SMPS8_SW)
VSMPS9: C271.1 L20.2 R742.2(P2)
VSMPS9_SW: L20.1 U3.M7(SMPS9_SW) U3.N7(SMPS9_SW)
N12220066: C108.1 C109.1 C110.1 C111.1 U9.13(PFBIN1) U9.15(PFBOUT) U9.24(PFBIN2)
N12225140: J5.11 R122.1(P1)
N12225158: C123.1 C124.1 C125.1 C126.1 U13.13(PFBIN1) U13.15(PFBOUT) U13.24(PFBIN2)
N12225278: J5.10 R151.1(P1)
N12226470: J5.9 R134.1(P1)
N12226568: R153.1(P1) R154.1(P1) U69.1(A)
N15911835: R147.2(P2) U13.16(RBIAS)
N16700927: J5.12 R138.1(P1)
N16818596: J3.9 R89.1(P1)
N16818719: R107.1(P1) R112.1(P1) U68.1(A)
N16819128: R103.2(P2) U9.16(RBIAS)
N17074741: J3.10 R106.1(P1)
N17569906: J12.11 R337.2
N17569909: J12.14 R340.2
N17569918: R341.1 U24.48(ISET)
N17569921: TP17.1 U24.41(CLK125_NDO)
N17570093: C193.2 R349.2(P2) U25.1(Xin/CLK) Y4.2
N17570094: C194.2 R349.1(P1) R351.2(P2) Y4.1
N17570107: R351.1(P1) U25.14(XOUT)
N17570112: R354.1 U25.11(Y1)
N17570113: R357.1 U25.9(Y2)
N17570114: R359.1 U25.8(Y3)
N17570122: R358.1(P1) U25.12(S2/SCL)
N17570123: R356.1(P1) U25.13(S1/SDA)
N17594977: C134.1 C135.1 C136.1 C138.1 U15.13(PFBIN1) U15.15(PFBOUT) U15.24(PFBIN2)
N17595008: J6.9 R172.1(P1)
N17595032: R190.1(P1) R195.1(P1) U70.1(A)
N17595048: R186.2(P2) U15.16(RBIAS)
N17595072: J6.10 R189.1(P1)
N17595076: J6.11 R161.1(P1)
N17595078: J6.12 R176.1(P1)
N17596821: J8.11 R203.1(P1)
N17596823: C147.1 C148.1 C149.1 C150.1 U17.13(PFBIN1) U17.15(PFBOUT) U17.24(PFBIN2)
N17596838: J8.10 R230.1(P1) R231.2(P2)
N17596847: R230.2(P2) U1.C17(MCASP3_AXR1/PR2_MII1_RXLINK)
N17596886: J8.9 R214.1(P1)
N17596899: R233.1(P1) R234.1(P1) U71.1(A)
N17596976: R228.2(P2) U17.16(RBIAS)
N17596979: J8.12 R218.1(P1)
N17863265: J3.11 R78.1(P1)
N17863276: J3.12 R93.1(P1)
N19258097: R546.1(P1) U45.7(OE)
N19258128: U45.21(XIN) Y7.3(CLK)
N19258198: R547.1(P1) Y7.1(OE)
N19258383: R548.1(P1) U45.11(OS0)
N19258403: R549.1(P1) R550.1(P1) U45.10(OS1)
N19258622: C305.1 U45.17(REG_CAP2)
N19258627: C306.1 U45.19(REG_CAP1)
N19415733: R568.1(P1) U45.12(RSTn)
N20275163: C460.1 U79.8(SS)
N20287248: R647.1(P1) R648.2(P2) U79.2(FB)
N20287275: R646.2(P2) U79.1(COMP)
N20287568: C463.1 R646.1(P1)
N20287584: D20.2(ANODE) L28.2 U79.5(SW)
N20301491: J52.A1 R649.1(P1) R650.2(P2)
N20338433: J52.B11 R654.1(P1) R655.2(P2)
N20537306: U44.2(A) U85.4(Y)
N20594970: R678.1(P1) U86.1(VEN)
N20595300: R679.1(P1) U79.3(EN)
N20619479: R680.2 R681.2 U86.2(ADJ)
N20664562: L22.1 U62.B1(L1) U62.B2(L1)
N20664572: C417.1 U62.A3(VINA) U62.B3(VINA1) U62.C4(~{PS}) U62.D4(VSEL)
N20665027: L22.2 U62.D1(L2) U62.D2(L2)

Not connected (* = marked no-connect by the designer): J3 7; J5 7; J6 7; J8 7; J12 2; J52 A19* A25* A26* A29* A30* A32* B12* B17* B23* B24* B27* B28* B30*; U9 22(XO)*; U13 22(XO)*; U15 22(XO)*; U17 22(XO)*; U24 45(XO)*; U25 2(S0)* 4(Vctr)*; U26 1(NC)*; U30 4(NC1)* 9(NC2)*; U45 8(NC8)* 13(NC13)* 15(NC15)* 23(OSCOUT) 24(NC24)* 25(NC25)* 26(NC26)* 27(NC27)* 28(NC28)* 29(NC29)* 30(NC30)* 31(NC31)* 32(NC32)*

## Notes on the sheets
sheet 21
- PR2_EDC_LATCH0 (ES2.0)
- PR1_EDC_LATCH0 (ES2.0)
- Note: MDIO Address = 0x01
sheet 22
- AM57XX_PR1_PROFI_TXEN
- PR1_EDC_SYNC0
- Note: MDIO Address = 0x01
sheet 23
- Note: MDIO Address = 0x00
sheet 24
- PR1_EDC_SYNC0 (ES2.0)
- PR2_EDC_SYNC0 (ES2.0)
- Note: MDIO Address = 0x00
sheet 25
- SD/MMC1 Connector
